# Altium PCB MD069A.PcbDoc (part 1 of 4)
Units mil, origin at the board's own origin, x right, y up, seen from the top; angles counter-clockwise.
Board outline 4569 x 3239 mil, 4 copper layers (Top Layer, Signal Layer 1, Signal Layer 2, Bottom Layer), stack 61.2 mil thick; 187 components, 103 nets, 560 pads, 220 vias.
Unrouted connection lines stored in the file: 7.
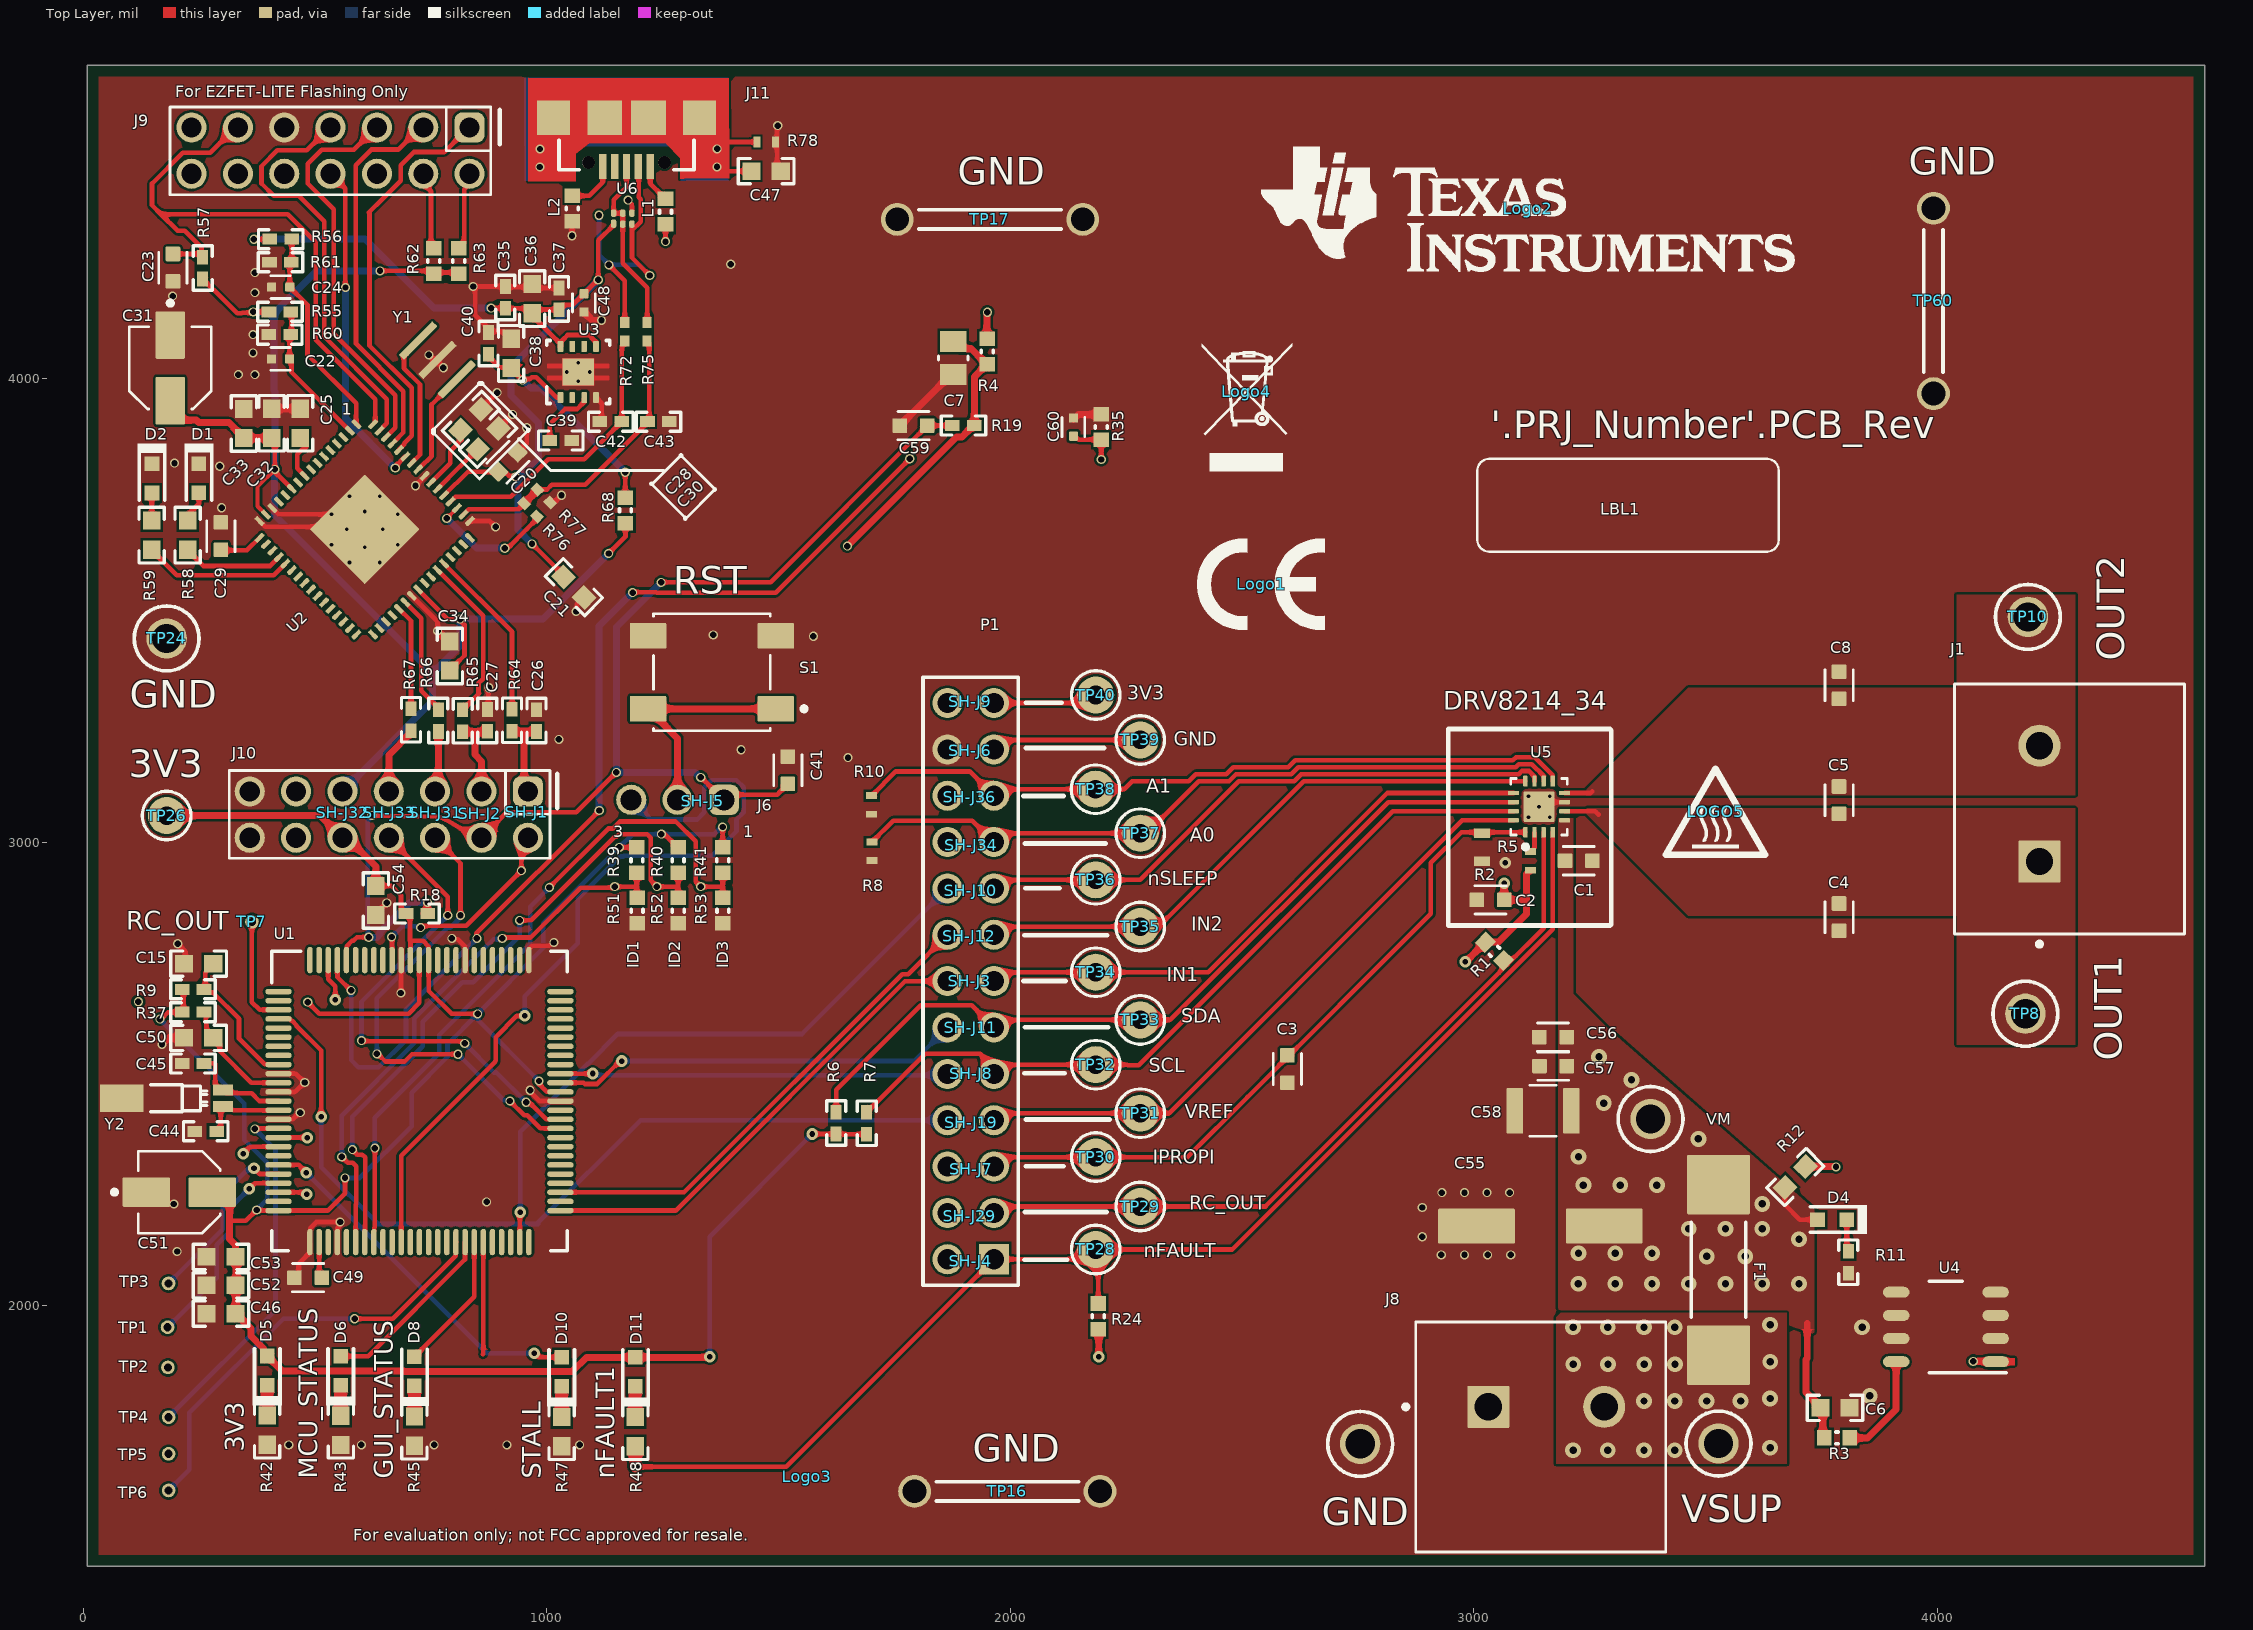
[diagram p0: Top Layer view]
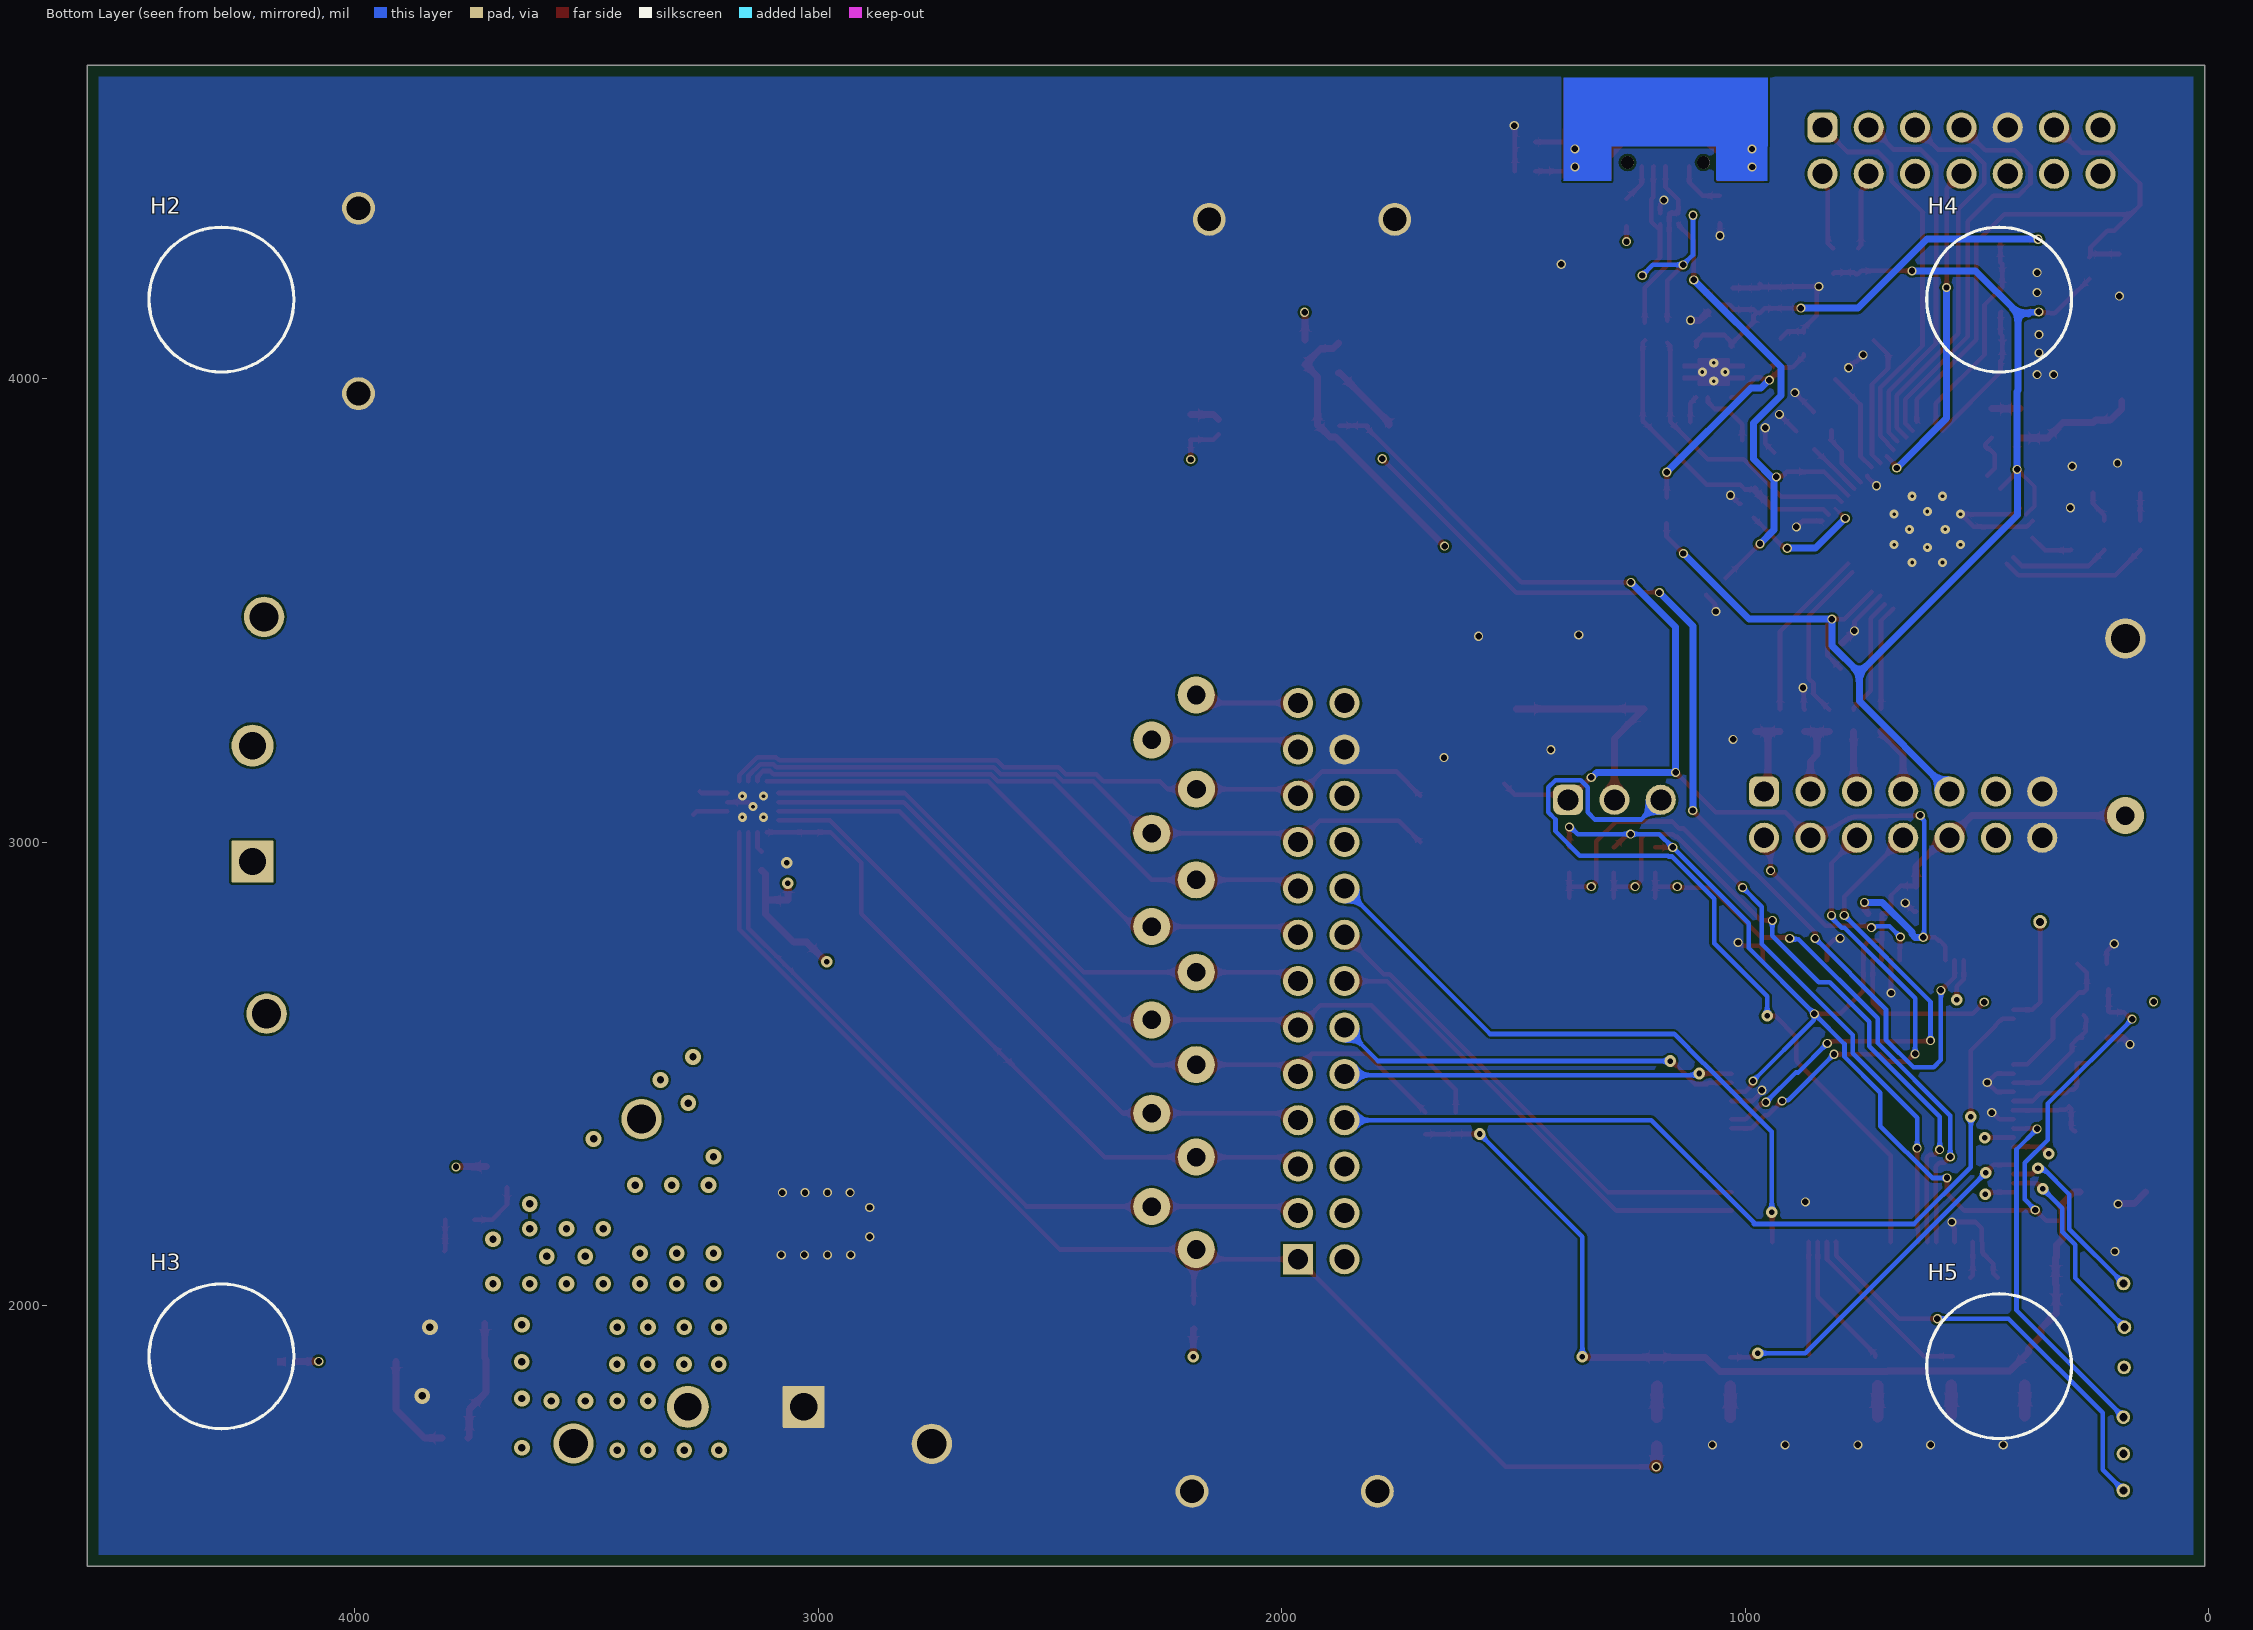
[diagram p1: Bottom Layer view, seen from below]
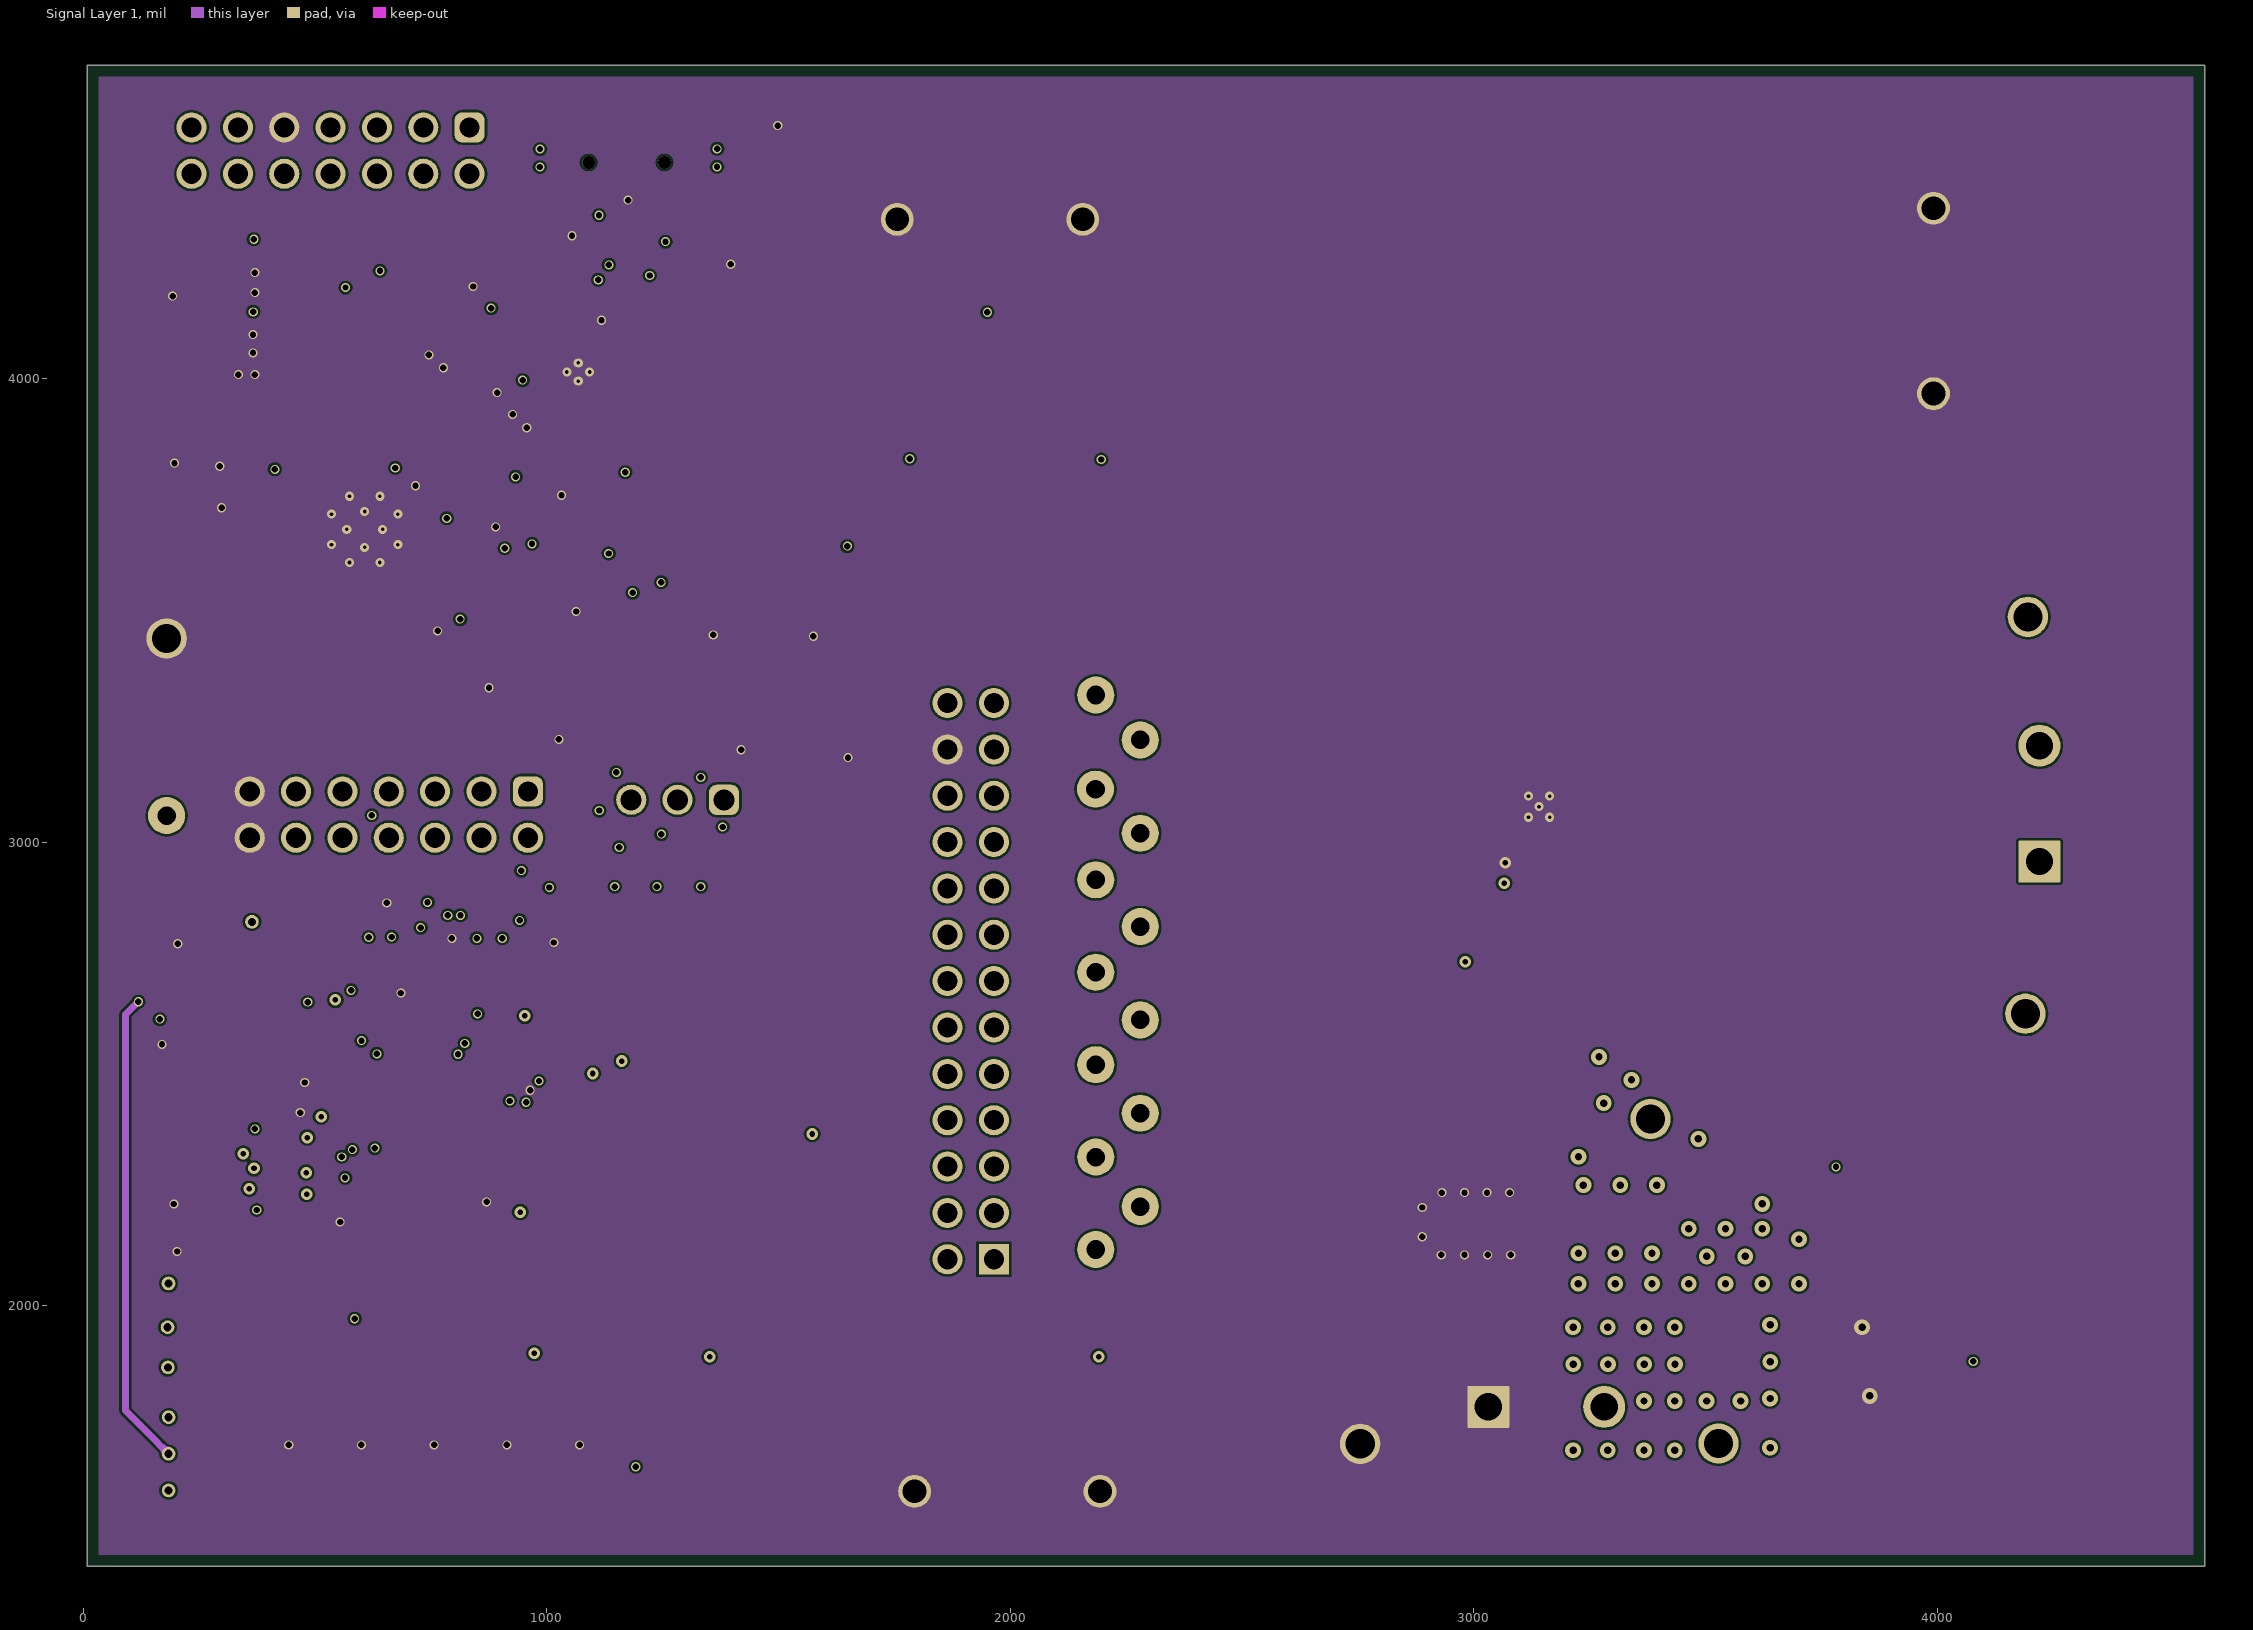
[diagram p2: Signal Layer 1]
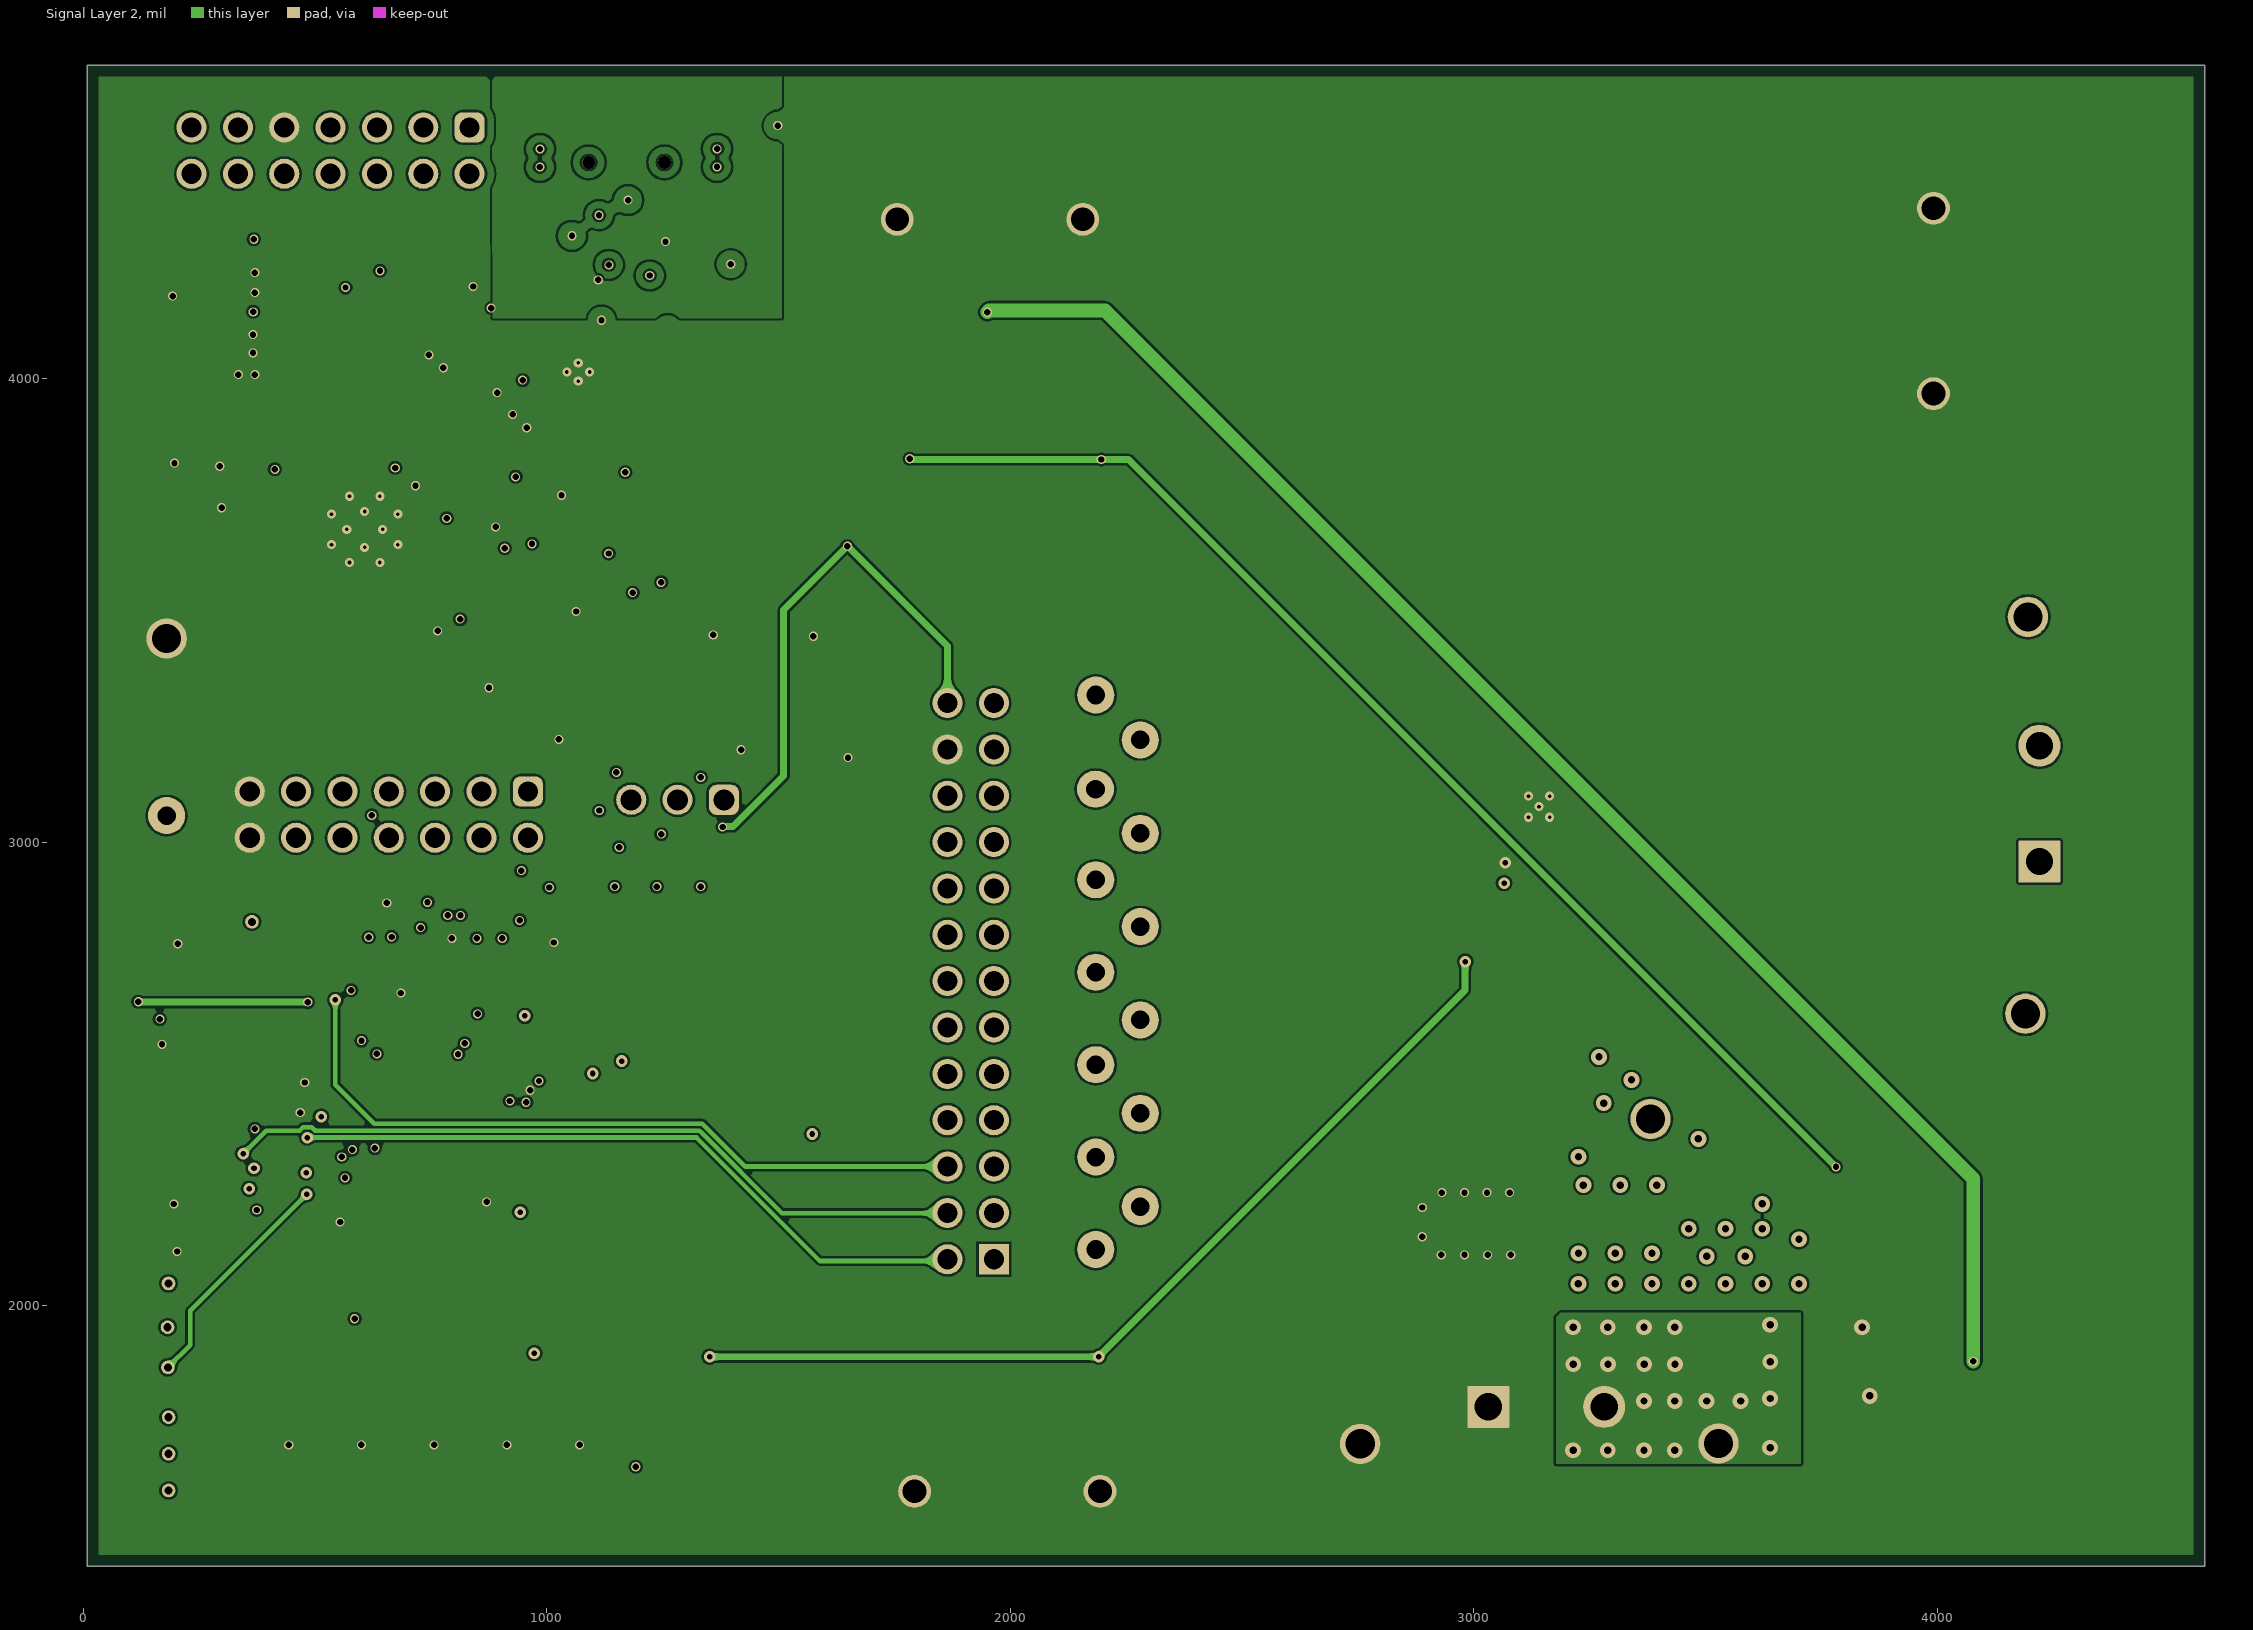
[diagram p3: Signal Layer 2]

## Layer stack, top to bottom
Top Solder: solder mask 0.4, Solder Resist, Dk 3.5
Top Layer: signal copper 2.8
Dielectric 1: prepreg 11.4, FR4 370, Dk 4.2
Signal Layer 1: signal copper 1.4
Dielectric 2: core 30, FR4 370, Dk 4.2
Signal Layer 2: signal copper 1.4
Dielectric 3: prepreg 11.4, FR4 370, Dk 4.2
Bottom Layer: signal copper 2.8
Bottom Solder: solder mask 0.4, Solder Resist, Dk 3.5

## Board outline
8,4677 8,1438 4577,1438 4577,4677

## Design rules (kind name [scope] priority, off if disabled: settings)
AcuteAngle [All] p1: minimum=4.50000000000000E+0001 checktracksonly=FALSE
AssemblyTestPointUsage [All] p1: valid=2
BoardOutlineClearance BoardOutlineClearance_MountingHoles [OnCopper and InComponentClass('Mounting Holes')] p1: gap=39.37 ignorepadtopadclearanceinfootprint=FALSE
BoardOutlineClearance BoardOutlineClearance_Poly [OnCopper and IsPoly] p2: gap=25 ignorepadtopadclearanceinfootprint=FALSE
BoardOutlineClearance [OnCopper and Not InComponentClass('Logo') and not InComponentClass('FiducialMark') and not InRegion(1000,500,4000,800) and not InPoly] p3: gap=75 ignorepadtopadclearanceinfootprint=FALSE
Clearance Clearance_92 [InNamedPolygon('TOP_LAYER_VM_P125')] p1: gap=8 ignorepadtopadclearanceinfootprint=TRUE
Clearance Clearance_93 [All] p2: gap=5 ignorepadtopadclearanceinfootprint=TRUE
Clearance Clearance_91 [InNamedPolygon('BOTTOM_LAYER_VM_P080')] p3: gap=10 ignorepadtopadclearanceinfootprint=TRUE except(0: Arc-Hole Track-Hole SMDPad-Hole THPad-Hole Via-Hole Fill-Hole Poly-Hole Region-Hole Text-Hole)
Clearance Clearance_90 [InNamedPolygon('BOTTOM_LAYER_OUT2_P211')] p4: gap=10 ignorepadtopadclearanceinfootprint=TRUE except(0: Arc-Hole Track-Hole SMDPad-Hole THPad-Hole Via-Hole Fill-Hole Poly-Hole Region-Hole Text-Hole)
Clearance Clearance_89 [InNamedPolygon('BOTTOM_LAYER_OUT1_P205')] p5: gap=10 ignorepadtopadclearanceinfootprint=TRUE except(0: Arc-Hole Track-Hole SMDPad-Hole THPad-Hole Via-Hole Fill-Hole Poly-Hole Region-Hole Text-Hole)
Clearance Clearance_88 [InNamedPolygon('BOTTOM_LAYER_OUT1_P205')] p6: gap=10 ignorepadtopadclearanceinfootprint=TRUE except(0: Arc-Hole Track-Hole SMDPad-Hole THPad-Hole Via-Hole Fill-Hole Poly-Hole Region-Hole Text-Hole)
Clearance Clearance_87 [InNamedPolygon('BOTTOM_LAYER_GND_P204')] p7: gap=10 ignorepadtopadclearanceinfootprint=TRUE except(0: Arc-Hole Track-Hole SMDPad-Hole THPad-Hole Via-Hole Fill-Hole Poly-Hole Region-Hole Text-Hole)
Clearance Clearance_86 [InNamedPolygon('TOP_LAYER_NONET_P237')] p8: gap=10 ignorepadtopadclearanceinfootprint=TRUE except(0: Arc-Hole Track-Hole SMDPad-Hole THPad-Hole Via-Hole Fill-Hole Poly-Hole Region-Hole Text-Hole)
Clearance Clearance_85 [InNamedPolygon('TOP_LAYER_VM_P229')] p9: gap=10 ignorepadtopadclearanceinfootprint=TRUE except(0: Arc-Hole Track-Hole SMDPad-Hole THPad-Hole Via-Hole Fill-Hole Poly-Hole Region-Hole Text-Hole)
Clearance Clearance_84 [InNamedPolygon('TOP_LAYER_GND_P086')] p10: gap=10 ignorepadtopadclearanceinfootprint=TRUE except(0: Arc-Hole Track-Hole SMDPad-Hole THPad-Hole Via-Hole Fill-Hole Poly-Hole Region-Hole Text-Hole)
Clearance Clearance_83 [InNamedPolygon('TOP_LAYER_OUT1_P221')] p11: gap=3.94 ignorepadtopadclearanceinfootprint=TRUE except(0: Arc-Hole Track-Hole SMDPad-Hole THPad-Hole Via-Hole Fill-Hole Poly-Hole Region-Hole Text-Hole)
Clearance Clearance_82 [InNamedPolygon('TOP_LAYER_OUT2_P173')] p12: gap=10 ignorepadtopadclearanceinfootprint=TRUE except(0: Arc-Hole Track-Hole SMDPad-Hole THPad-Hole Via-Hole Fill-Hole Poly-Hole Region-Hole Text-Hole)
Clearance Clearance_81 [InNamedPolygon('TOP_LAYER_OUT2_P173')] p13: gap=10 ignorepadtopadclearanceinfootprint=TRUE except(0: Arc-Hole Track-Hole SMDPad-Hole THPad-Hole Via-Hole Fill-Hole Poly-Hole Region-Hole Text-Hole)
Clearance Clearance_80 [InNamedPolygon('TOP_LAYER_OUT2_P173')] p14: gap=10 ignorepadtopadclearanceinfootprint=TRUE except(0: Arc-Hole Track-Hole SMDPad-Hole THPad-Hole Via-Hole Fill-Hole Poly-Hole Region-Hole Text-Hole)
Clearance Clearance_79 [InNamedPolygon('TOP_LAYER_OUT1_P221')] p15: gap=10 ignorepadtopadclearanceinfootprint=TRUE except(0: Arc-Hole Track-Hole SMDPad-Hole THPad-Hole Via-Hole Fill-Hole Poly-Hole Region-Hole Text-Hole)
Clearance Clearance_78 [InNamedPolygon('TOP_LAYER_GND_P086')] p16: gap=10 ignorepadtopadclearanceinfootprint=TRUE except(0: Arc-Hole Track-Hole SMDPad-Hole THPad-Hole Via-Hole Fill-Hole Poly-Hole Region-Hole Text-Hole)
Clearance Clearance_77 [InNamedPolygon('TOP_LAYER_OUT1_P129')] p17: gap=10 ignorepadtopadclearanceinfootprint=TRUE except(0: Arc-Hole Track-Hole SMDPad-Hole THPad-Hole Via-Hole Fill-Hole Poly-Hole Region-Hole Text-Hole)
Clearance Clearance_76 [InNamedPolygon('TOP_LAYER_OUT2_P173')] p18: gap=10 ignorepadtopadclearanceinfootprint=TRUE except(0: Arc-Hole Track-Hole SMDPad-Hole THPad-Hole Via-Hole Fill-Hole Poly-Hole Region-Hole Text-Hole)
Clearance Clearance_75 [InNamedPolygon('TOP_LAYER_VM_P085')] p19: gap=10 ignorepadtopadclearanceinfootprint=TRUE except(0: Arc-Hole Track-Hole SMDPad-Hole THPad-Hole Via-Hole Fill-Hole Poly-Hole Region-Hole Text-Hole)
Clearance Clearance_74 [InNamedPolygon('TOP_LAYER_GND_P121')] p20: gap=10 ignorepadtopadclearanceinfootprint=TRUE except(0: Arc-Hole Track-Hole SMDPad-Hole THPad-Hole Via-Hole Fill-Hole Poly-Hole Region-Hole Text-Hole)
Clearance Clearance_73 [InNamedPolygon('TOP_LAYER_OUT1_P129') Or  InNamedPolygon('TOP_LAYER_OUT2_P173')] p21: gap=1.97 ignorepadtopadclearanceinfootprint=TRUE except(0: Arc-Hole Track-Hole SMDPad-Hole THPad-Hole Via-Hole Fill-Hole Poly-Hole Region-Hole Text-Hole)
Clearance Clearance_72 [InNamedPolygon('TOP_LAYER_OUT2_P173') Or  InNamedPolygon('TOP_LAYER_OUT1_P129')] p22: gap=3.94 ignorepadtopadclearanceinfootprint=TRUE except(0: Arc-Hole Track-Hole SMDPad-Hole THPad-Hole Via-Hole Fill-Hole Poly-Hole Region-Hole Text-Hole)
Clearance Clearance_71 [InNamedPolygon('TOP_LAYER_OUT2_P173')] p23: gap=10 ignorepadtopadclearanceinfootprint=TRUE except(0: Arc-Hole Track-Hole SMDPad-Hole THPad-Hole Via-Hole Fill-Hole Poly-Hole Region-Hole Text-Hole)
Clearance Clearance_70 [InNamedPolygon('TOP_LAYER_OUT1_P129')] p24: gap=10 ignorepadtopadclearanceinfootprint=TRUE except(0: Arc-Hole Track-Hole SMDPad-Hole THPad-Hole Via-Hole Fill-Hole Poly-Hole Region-Hole Text-Hole)
Clearance Clearance_69 [InNamedPolygon('TOP_LAYER_OUT2_P173')] p25: gap=3.94 ignorepadtopadclearanceinfootprint=TRUE except(0: Arc-Hole Track-Hole SMDPad-Hole THPad-Hole Via-Hole Fill-Hole Poly-Hole Region-Hole Text-Hole)
Clearance Clearance_68 [InNamedPolygon('TOP_LAYER_OUT1_P129')] p26: gap=3.94 ignorepadtopadclearanceinfootprint=TRUE except(0: Arc-Hole Track-Hole SMDPad-Hole THPad-Hole Via-Hole Fill-Hole Poly-Hole Region-Hole Text-Hole)
Clearance Clearance_67 [InNamedPolygon('TOP_LAYER_VM_P085')] p27: gap=3.94 ignorepadtopadclearanceinfootprint=TRUE except(0: Arc-Hole Track-Hole SMDPad-Hole THPad-Hole Via-Hole Fill-Hole Poly-Hole Region-Hole Text-Hole)
Clearance Clearance_66 [InNamedPolygon('BOTTOM_LAYER_P_IN_P174')] p28: gap=10 ignorepadtopadclearanceinfootprint=TRUE except(0: Arc-Hole Track-Hole SMDPad-Hole THPad-Hole Via-Hole Fill-Hole Poly-Hole Region-Hole Text-Hole)
Clearance Clearance_65 [InNamedPolygon('BOTTOM_LAYER_NETF1_2_P203')] p29: gap=10 ignorepadtopadclearanceinfootprint=TRUE except(0: Arc-Hole Track-Hole SMDPad-Hole THPad-Hole Via-Hole Fill-Hole Poly-Hole Region-Hole Text-Hole)
Clearance Clearance_64 [InNamedPolygon('BOTTOM_LAYER_VBAT_P165')] p30: gap=10 ignorepadtopadclearanceinfootprint=TRUE except(0: Arc-Hole Track-Hole SMDPad-Hole THPad-Hole Via-Hole Fill-Hole Poly-Hole Region-Hole Text-Hole)
Clearance Clearance_63 [InNamedPolygon('TOP_LAYER_VM_P167')] p31: gap=10 ignorepadtopadclearanceinfootprint=TRUE except(0: Arc-Hole Track-Hole SMDPad-Hole THPad-Hole Via-Hole Fill-Hole Poly-Hole Region-Hole Text-Hole)
Clearance Clearance_62 [InNamedPolygon('TOP_LAYER_VM_P167')] p32: gap=10 ignorepadtopadclearanceinfootprint=TRUE except(0: Arc-Hole Track-Hole SMDPad-Hole THPad-Hole Via-Hole Fill-Hole Poly-Hole Region-Hole Text-Hole)
Clearance Clearance_61 [InNamedPolygon('TOP_LAYER_VM_P171')] p33: gap=10 ignorepadtopadclearanceinfootprint=TRUE except(0: Arc-Hole Track-Hole SMDPad-Hole THPad-Hole Via-Hole Fill-Hole Poly-Hole Region-Hole Text-Hole)
Clearance Clearance_60 [InNamedPolygon('SIGNAL_LAYER_2_NETF1_2_P196')] p34: gap=10 ignorepadtopadclearanceinfootprint=TRUE except(0: Arc-Hole Track-Hole SMDPad-Hole THPad-Hole Via-Hole Fill-Hole Poly-Hole Region-Hole Text-Hole)
Clearance Clearance_59 [InNamedPolygon('SIGNAL_LAYER_2_VBAT_P197')] p35: gap=10 ignorepadtopadclearanceinfootprint=TRUE except(0: Arc-Hole Track-Hole SMDPad-Hole THPad-Hole Via-Hole Fill-Hole Poly-Hole Region-Hole Text-Hole)
Clearance Clearance_58 [InNamedPolygon('SIGNAL_LAYER_2_P_IN_P198')] p36: gap=10 ignorepadtopadclearanceinfootprint=TRUE except(0: Arc-Hole Track-Hole SMDPad-Hole THPad-Hole Via-Hole Fill-Hole Poly-Hole Region-Hole Text-Hole)
Clearance Clearance_57 [InNamedPolygon('SIGNAL_LAYER_2_3V3_P194')] p37: gap=10 ignorepadtopadclearanceinfootprint=TRUE except(0: Arc-Hole Track-Hole SMDPad-Hole THPad-Hole Via-Hole Fill-Hole Poly-Hole Region-Hole Text-Hole)
Clearance Clearance_56 [InNamedPolygon('TOP_LAYER_NETF1_2_P207')] p38: gap=10 ignorepadtopadclearanceinfootprint=TRUE except(0: Arc-Hole Track-Hole SMDPad-Hole THPad-Hole Via-Hole Fill-Hole Poly-Hole Region-Hole Text-Hole)
Clearance Clearance_55 [InNamedPolygon('TOP_LAYER_VBAT_P223')] p39: gap=10 ignorepadtopadclearanceinfootprint=TRUE except(0: Arc-Hole Track-Hole SMDPad-Hole THPad-Hole Via-Hole Fill-Hole Poly-Hole Region-Hole Text-Hole)
Clearance Clearance_54 [InNamedPolygon('TOP_LAYER_P_IN_P227')] p40: gap=10 ignorepadtopadclearanceinfootprint=TRUE except(0: Arc-Hole Track-Hole SMDPad-Hole THPad-Hole Via-Hole Fill-Hole Poly-Hole Region-Hole Text-Hole)
Clearance Clearance_53 [InNamedPolygon('TOP_LAYER_GND_P086')] p41: gap=10 ignorepadtopadclearanceinfootprint=TRUE except(0: Arc-Hole Track-Hole SMDPad-Hole THPad-Hole Via-Hole Fill-Hole Poly-Hole Region-Hole Text-Hole)
Clearance Clearance_52 [InNamedPolygon('SIGNAL_LAYER_2_VM_P177') Or  InNamedPolygon('SIGNAL_LAYER_2_VM_P179') Or  InNamedPolygon('SIGNAL_LAYER_2_VM_P160') Or  InNamedPolygon('SIGNAL_LAYER_2_VM_P175') Or  InNamedPolygon('SIGNAL_LAYER_2_VM_P181')] p42: gap=10 ignorepadtopadclearanceinfootprint=TRUE except(0: Arc-Hole Track-Hole SMDPad-Hole THPad-Hole Via-Hole Fill-Hole Poly-Hole Region-Hole Text-Hole)
Clearance Clearance_51 [InNamedPolygon('SIGNAL_LAYER_2_EZFET_VBUS_P136')] p43: gap=10 ignorepadtopadclearanceinfootprint=TRUE except(0: Arc-Hole Track-Hole SMDPad-Hole THPad-Hole Via-Hole Fill-Hole Poly-Hole Region-Hole Text-Hole)
Clearance Clearance_50 [InNamedPolygon('SIGNAL_LAYER_2_EZFET_VCC_P132')] p44: gap=10 ignorepadtopadclearanceinfootprint=TRUE except(0: Arc-Hole Track-Hole SMDPad-Hole THPad-Hole Via-Hole Fill-Hole Poly-Hole Region-Hole Text-Hole)
Clearance Clearance_49 [InNamedPolygon('SIGNAL_LAYER_2_MCU_3V3_P192')] p45: gap=10 ignorepadtopadclearanceinfootprint=TRUE except(0: Arc-Hole Track-Hole SMDPad-Hole THPad-Hole Via-Hole Fill-Hole Poly-Hole Region-Hole Text-Hole)
Clearance Clearance_48 [InNamedPolygon('SIGNAL_LAYER_1_GND_P190')] p46: gap=10 ignorepadtopadclearanceinfootprint=TRUE except(0: Arc-Hole Track-Hole SMDPad-Hole THPad-Hole Via-Hole Fill-Hole Poly-Hole Region-Hole Text-Hole)
Clearance Clearance_47 [InNamedPolygon('SIGNAL_LAYER_1_GND_P184')] p47: gap=10 ignorepadtopadclearanceinfootprint=TRUE except(0: Arc-Hole Track-Hole SMDPad-Hole THPad-Hole Via-Hole Fill-Hole Poly-Hole Region-Hole Text-Hole)
Clearance Clearance_46 [InNamedPolygon('BOTTOM_LAYER_GND_P241')] p48: gap=10 ignorepadtopadclearanceinfootprint=TRUE except(0: Arc-Hole Track-Hole SMDPad-Hole THPad-Hole Via-Hole Fill-Hole Poly-Hole Region-Hole Text-Hole)
Clearance Clearance_45 [InNamedPolygon('BOTTOM_LAYER_GND_P241')] p49: gap=10 ignorepadtopadclearanceinfootprint=TRUE except(0: Arc-Hole Track-Hole SMDPad-Hole THPad-Hole Via-Hole Fill-Hole Poly-Hole Region-Hole Text-Hole)
Clearance Clearance_44 [InNamedPolygon('BOTTOM_LAYER_OUT2_P163')] p50: gap=10 ignorepadtopadclearanceinfootprint=TRUE except(0: Arc-Hole Track-Hole SMDPad-Hole THPad-Hole Via-Hole Fill-Hole Poly-Hole Region-Hole Text-Hole)
Clearance Clearance_43 [InNamedPolygon('BOTTOM_LAYER_VM_P166')] p51: gap=10 ignorepadtopadclearanceinfootprint=TRUE except(0: Arc-Hole Track-Hole SMDPad-Hole THPad-Hole Via-Hole Fill-Hole Poly-Hole Region-Hole Text-Hole)
Clearance Clearance_42 [InNamedPolygon('BOTTOM_LAYER_VM_P235')] p52: gap=10 ignorepadtopadclearanceinfootprint=TRUE except(0: Arc-Hole Track-Hole SMDPad-Hole THPad-Hole Via-Hole Fill-Hole Poly-Hole Region-Hole Text-Hole)
Clearance Clearance_41 [InNamedPolygon('BOTTOM_LAYER_OUT1_P164')] p53: gap=10 ignorepadtopadclearanceinfootprint=TRUE except(0: Arc-Hole Track-Hole SMDPad-Hole THPad-Hole Via-Hole Fill-Hole Poly-Hole Region-Hole Text-Hole)
Clearance Clearance_40 [InNamedPolygon('BOTTOM_LAYER_GND_P162')] p54: gap=10 ignorepadtopadclearanceinfootprint=TRUE except(0: Arc-Hole Track-Hole SMDPad-Hole THPad-Hole Via-Hole Fill-Hole Poly-Hole Region-Hole Text-Hole)
Clearance Clearance_39 [InNamedPolygon('SIGNAL_LAYER_2_VM_P160')] p55: gap=10 ignorepadtopadclearanceinfootprint=TRUE except(0: Arc-Hole Track-Hole SMDPad-Hole THPad-Hole Via-Hole Fill-Hole Poly-Hole Region-Hole Text-Hole)
Clearance Clearance_38 [InNamedPolygon('SIGNAL_LAYER_2_NONET_P138')] p56: gap=10 ignorepadtopadclearanceinfootprint=TRUE except(0: Arc-Hole Track-Hole SMDPad-Hole THPad-Hole Via-Hole Fill-Hole Poly-Hole Region-Hole Text-Hole)
Clearance Clearance_37 [InNamedPolygon('SIGNAL_LAYER_1_VM_P146')] p57: gap=10 ignorepadtopadclearanceinfootprint=TRUE except(0: Arc-Hole Track-Hole SMDPad-Hole THPad-Hole Via-Hole Fill-Hole Poly-Hole Region-Hole Text-Hole)
Clearance Clearance_36 [InNamedPolygon('SIGNAL_LAYER_2_GND_P156')] p58: gap=10 ignorepadtopadclearanceinfootprint=TRUE except(0: Arc-Hole Track-Hole SMDPad-Hole THPad-Hole Via-Hole Fill-Hole Poly-Hole Region-Hole Text-Hole)
Clearance Clearance_35 [InNamedPolygon('SIGNAL_LAYER_1_VM_P148') Or  InNamedPolygon('SIGNAL_LAYER_1_VM_P148')] p59: gap=10 ignorepadtopadclearanceinfootprint=TRUE except(0: Arc-Hole Track-Hole SMDPad-Hole THPad-Hole Via-Hole Fill-Hole Poly-Hole Region-Hole Text-Hole)
Clearance Clearance_34 [InNamedPolygon('SIGNAL_LAYER_1_GND_P154')] p60: gap=10 ignorepadtopadclearanceinfootprint=TRUE except(0: Arc-Hole Track-Hole SMDPad-Hole THPad-Hole Via-Hole Fill-Hole Poly-Hole Region-Hole Text-Hole)
Clearance Clearance_33 [InNamedPolygon('SIGNAL_LAYER_2_NONET_P138')] p61: gap=10 ignorepadtopadclearanceinfootprint=TRUE except(0: Arc-Hole Track-Hole SMDPad-Hole THPad-Hole Via-Hole Fill-Hole Poly-Hole Region-Hole Text-Hole)
Clearance Clearance_32 [InNamedPolygon('SIGNAL_LAYER_2_GND_P082')] p62: gap=10 ignorepadtopadclearanceinfootprint=TRUE except(0: Arc-Hole Track-Hole SMDPad-Hole THPad-Hole Via-Hole Fill-Hole Poly-Hole Region-Hole Text-Hole)
Clearance Clearance_31 [InNamedPolygon('TOP_LAYER_GND_P076')] p63: gap=10 ignorepadtopadclearanceinfootprint=TRUE except(0: Arc-Hole Track-Hole SMDPad-Hole THPad-Hole Via-Hole Fill-Hole Poly-Hole Region-Hole Text-Hole)
Clearance Clearance_30 [InNamedPolygon('TOP_LAYER_GND_P087')] p64: gap=10 ignorepadtopadclearanceinfootprint=TRUE except(0: Arc-Hole Track-Hole SMDPad-Hole THPad-Hole Via-Hole Fill-Hole Poly-Hole Region-Hole Text-Hole)
Clearance Clearance_29 [InNamedPolygon('TOP_LAYER_VM_P127') Or  InNamedPolygon('TOP_LAYER_VM_P085')] p65: gap=10 ignorepadtopadclearanceinfootprint=TRUE except(0: Arc-Hole Track-Hole SMDPad-Hole THPad-Hole Via-Hole Fill-Hole Poly-Hole Region-Hole Text-Hole)
Clearance Clearance_28 [InNamedPolygon('TOP_LAYER_GND_P117')] p66: gap=10 ignorepadtopadclearanceinfootprint=TRUE except(0: Arc-Hole Track-Hole SMDPad-Hole THPad-Hole Via-Hole Fill-Hole Poly-Hole Region-Hole Text-Hole)
Clearance Clearance_27 [InNamedPolygon('TOP_LAYER_OUT1_P129') Or  InNamedPolygon('TOP_LAYER_OUT2_P173')] p67: gap=10 ignorepadtopadclearanceinfootprint=TRUE except(0: Arc-Hole Track-Hole SMDPad-Hole THPad-Hole Via-Hole Fill-Hole Poly-Hole Region-Hole Text-Hole)
Clearance Clearance_26 [InNamedPolygon('SIGNAL_LAYER_2_NONET_P113')] p68: gap=10 ignorepadtopadclearanceinfootprint=TRUE except(0: Arc-Hole Track-Hole SMDPad-Hole THPad-Hole Via-Hole Fill-Hole Poly-Hole Region-Hole Text-Hole)
Clearance Clearance_25 [InNamedPolygon('BOTTOM_LAYER_NONET_P115')] p69: gap=10 ignorepadtopadclearanceinfootprint=TRUE except(0: Arc-Hole Track-Hole SMDPad-Hole THPad-Hole Via-Hole Fill-Hole Poly-Hole Region-Hole Text-Hole)
Clearance Clearance_24 [InNamedPolygon('SIGNAL_LAYER_1_NONET_P111')] p70: gap=10 ignorepadtopadclearanceinfootprint=TRUE except(0: Arc-Hole Track-Hole SMDPad-Hole THPad-Hole Via-Hole Fill-Hole Poly-Hole Region-Hole Text-Hole)
Clearance Clearance_23 [InNamedPolygon('TOP_LAYER_NONET_P083')] p71: gap=10 ignorepadtopadclearanceinfootprint=TRUE except(0: Arc-Hole Track-Hole SMDPad-Hole THPad-Hole Via-Hole Fill-Hole Poly-Hole Region-Hole Text-Hole)
Clearance Clearance_22 [InNamedPolygon('TOP_LAYER_NONET_P105')] p72: gap=10 ignorepadtopadclearanceinfootprint=TRUE except(0: Arc-Hole Track-Hole SMDPad-Hole THPad-Hole Via-Hole Fill-Hole Poly-Hole Region-Hole Text-Hole)
Clearance Clearance_21 [InNamedPolygon('TOP_LAYER_OUT2_P107')] p73: gap=10 ignorepadtopadclearanceinfootprint=TRUE except(0: Arc-Hole Track-Hole SMDPad-Hole THPad-Hole Via-Hole Fill-Hole Poly-Hole Region-Hole Text-Hole)
Clearance Clearance_20 [InNamedPolygon('TOP_LAYER_NONET_P101')] p74: gap=10 ignorepadtopadclearanceinfootprint=TRUE except(0: Arc-Hole Track-Hole SMDPad-Hole THPad-Hole Via-Hole Fill-Hole Poly-Hole Region-Hole Text-Hole)
Clearance Clearance_19 [InNamedPolygon('TOP_LAYER_OUT1_P103')] p75: gap=10 ignorepadtopadclearanceinfootprint=TRUE except(0: Arc-Hole Track-Hole SMDPad-Hole THPad-Hole Via-Hole Fill-Hole Poly-Hole Region-Hole Text-Hole)
Clearance Clearance_18 [InNet('OUT1')] p76: gap=10 ignorepadtopadclearanceinfootprint=TRUE except(0: Arc-Hole Track-Hole SMDPad-Hole THPad-Hole Via-Hole Fill-Hole Poly-Hole Region-Hole Text-Hole)
Clearance Clearance_17 [InNamedPolygon('TOP_LAYER_OUT1_P000')] p77: gap=10 ignorepadtopadclearanceinfootprint=TRUE except(0: Arc-Hole Track-Hole SMDPad-Hole THPad-Hole Via-Hole Fill-Hole Poly-Hole Region-Hole Text-Hole)
Clearance Clearance_16 [InNamedPolygon('TOP_LAYER_OUT1_P000') vs InNet('OUT1')] p78: gap=3.94 ignorepadtopadclearanceinfootprint=TRUE except(0: Arc-Hole Track-Hole SMDPad-Hole THPad-Hole Via-Hole Fill-Hole Poly-Hole Region-Hole Text-Hole)
Clearance Clearance_15 [InNamedPolygon('TOP_LAYER_OUT1_P000')] p79: gap=3.94 ignorepadtopadclearanceinfootprint=TRUE except(0: Arc-Hole Track-Hole SMDPad-Hole THPad-Hole Via-Hole Fill-Hole Poly-Hole Region-Hole Text-Hole)
Clearance Clearance_14 [InNamedPolygon('TOP_LAYER_NONET_P093')] p80: gap=3.94 ignorepadtopadclearanceinfootprint=TRUE except(0: Arc-Hole Track-Hole SMDPad-Hole THPad-Hole Via-Hole Fill-Hole Poly-Hole Region-Hole Text-Hole)
Clearance Clearance_13 [InNamedPolygon('TOP_LAYER_NONET_P093')] p81: gap=10 ignorepadtopadclearanceinfootprint=TRUE except(0: Arc-Hole Track-Hole SMDPad-Hole THPad-Hole Via-Hole Fill-Hole Poly-Hole Region-Hole Text-Hole)
Clearance Clearance_12 [InNamedPolygon('TOP_LAYER_OUT2_P099')] p82: gap=10 ignorepadtopadclearanceinfootprint=TRUE except(0: Arc-Hole Track-Hole SMDPad-Hole THPad-Hole Via-Hole Fill-Hole Poly-Hole Region-Hole Text-Hole)
Clearance Clearance_11 [InNamedPolygon('TOP_LAYER_OUT2_P099')] p83: gap=10 ignorepadtopadclearanceinfootprint=TRUE except(0: Arc-Hole Track-Hole SMDPad-Hole THPad-Hole Via-Hole Fill-Hole Poly-Hole Region-Hole Text-Hole)
Clearance Clearance_10 [InNamedPolygon('TOP_LAYER_OUT1_P000')] p84: gap=10 ignorepadtopadclearanceinfootprint=TRUE except(0: Arc-Hole Track-Hole SMDPad-Hole THPad-Hole Via-Hole Fill-Hole Poly-Hole Region-Hole Text-Hole)
Clearance Clearance_9 [InNamedPolygon('TOP_LAYER_OUT1_P000')] p85: gap=10 ignorepadtopadclearanceinfootprint=TRUE except(0: Arc-Hole Track-Hole SMDPad-Hole THPad-Hole Via-Hole Fill-Hole Poly-Hole Region-Hole Text-Hole)
Clearance Clearance_8 [InNamedPolygon('BOTTOM_LAYER_NONET_P079') Or  InNamedPolygon('SIGNAL_LAYER_2_NONET_P078') Or  InNamedPolygon('SIGNAL_LAYER_1_NONET_P077') Or  InNamedPolygon('TOP_LAYER_NONET_P083') Or  InNamedPolygon('BOTTOM_LAYER_NONET_P072') Or  InNamedPolygon('SIGNAL_LAYER_2_NONET_P070') Or  InNamedPolygon('SIGNAL_LAYER_1_NONET_P059') Or  InNamedPolygon('TOP_LAYER_OUT2_P058') Or  InNamedPolygon('BOTTOM_LAYER_NONET_P056') Or  InNamedPolygon('SIGNAL_LAYER_2_NONET_P054') Or  InNamedPolygon('SIGNAL_LAYER_1_NONET_P052') Or  InNamedPolygon('TOP_LAYER_OUT1_P050') Or  InNamedPolygon('BOTTOM_LAYER_VM_P044') Or  InNamedPolygon('SIGNAL_LAYER_2_VM_P042') Or  InNamedPolygon('SIGNAL_LAYER_1_VM_P040') Or  InNamedPolygon('TOP_LAYER_VM_P038') Or  InNamedPolygon('BOTTOM_LAYER_VM_P036') Or  InNamedPolygon('SIGNAL_LAYER_2_VM_P018') Or  InNamedPolygon('SIGNAL_LAYER_1_VM_P016') Or  InNamedPolygon('TOP_LAYER_VM_P002')] p86: gap=10 ignorepadtopadclearanceinfootprint=TRUE except(0: Arc-Hole Track-Hole SMDPad-Hole THPad-Hole Via-Hole Fill-Hole Poly-Hole Region-Hole Text-Hole)
Clearance Clearance_7 [InNamedPolygon('TOP_LAYER_NONET_P089') Or  InNamedPolygon('TOP_LAYER_NONET_P090')] p87: gap=10 ignorepadtopadclearanceinfootprint=TRUE except(0: Arc-Hole Track-Hole SMDPad-Hole THPad-Hole Via-Hole Fill-Hole Poly-Hole Region-Hole Text-Hole)
Clearance Clearance_6 [InNamedPolygon('BOTTOM_LAYER_EZFET_USB_SHIELD_P002') Or  InNamedPolygon('TOP_LAYER_EZFET_USB_SHIELD_P201') Or  InNamedPolygon('SIGNAL_LAYER_2_EZFET_VBUS_P018') Or  InNamedPolygon('SIGNAL_LAYER_2_EZFET_VCC_P016')] p88: gap=10 ignorepadtopadclearanceinfootprint=TRUE except(0: Arc-Hole Track-Hole SMDPad-Hole THPad-Hole Via-Hole Fill-Hole Poly-Hole Region-Hole Text-Hole)
Clearance Clearance_5 [InNamedPolygon('TOP_LAYER_NONET_P072')] p89: gap=10 ignorepadtopadclearanceinfootprint=TRUE except(0: Arc-Hole Track-Hole SMDPad-Hole THPad-Hole Via-Hole Fill-Hole Poly-Hole Region-Hole Text-Hole)
Clearance Clearance_4 [InNamedPolygon('TOP_LAYER_VM_P123') Or  InNamedPolygon('TOP_LAYER_VM_P123') Or  InNamedPolygon('TOP_LAYER_VM_P123')] p90: gap=10 ignorepadtopadclearanceinfootprint=TRUE except(0: Arc-Hole Track-Hole SMDPad-Hole THPad-Hole Via-Hole Fill-Hole Poly-Hole Region-Hole Text-Hole)
Clearance Clearance_3 [InNamedPolygon('TOP_LAYER_VM_P042') Or  InNamedPolygon('TOP_LAYER_VM_P044') Or  InNamedPolygon('TOP_LAYER_OUT2_P040') Or  InNamedPolygon('TOP_LAYER_OUT1_P038')] p91: gap=10 ignorepadtopadclearanceinfootprint=TRUE except(0: Arc-Hole Track-Hole SMDPad-Hole THPad-Hole Via-Hole Fill-Hole Poly-Hole Region-Hole Text-Hole)
Clearance Clearance_2 [InNamedPolygon('TOP_LAYER_OUT2_P040')] p92: gap=10 ignorepadtopadclearanceinfootprint=TRUE except(0: Arc-Hole Track-Hole SMDPad-Hole THPad-Hole Via-Hole Fill-Hole Poly-Hole Region-Hole Text-Hole)
Clearance Clearance_1 [InNamedPolygon('TOP_LAYER_VM_P046')] p93: gap=5.98 ignorepadtopadclearanceinfootprint=TRUE except(0: Arc-Hole Track-Hole SMDPad-Hole THPad-Hole Via-Hole Fill-Hole Poly-Hole Region-Hole Text-Hole)
Clearance Clearance_Keepouts [((IsTrack Or IsArc) And Not InPoly) And IsFree and IsKeepOut vs ((IsTrack Or IsArc) And Not InPoly) And IsFree and IsKeepOut] p94: gap=0 ignorepadtopadclearanceinfootprint=FALSE
Clearance Clearance_Poly [InPolygon] p95: gap=25 ignorepadtopadclearanceinfootprint=TRUE
Clearance Clearance_FiducialMark [IsKeepOut and InComponentClass('FiducialMark') vs IsPad and InComponentClass('FiducialMark')] p96: gap=0 ignorepadtopadclearanceinfootprint=FALSE
Clearance [All] p97: gap=7.87 ignorepadtopadclearanceinfootprint=TRUE
ComponentClearance ComponentClearance_MountingHoles_FiducialMarks [InComponentClass('Mounting Holes') vs InComponentClass('FiducialMark')] p1: gap=50 collisioncheckmode=3 verticalgap=10 showdistances=FALSE
ComponentClearance ComponentClearance_Shunt [InComponentClass('Header') vs InComponentClass('Shunt')] p2: gap=0 collisioncheckmode=3 verticalgap=0 showdistances=FALSE
ComponentClearance ComponentClearance_Logo [InComponentClass('Logo')] p3: gap=50 collisioncheckmode=3 verticalgap=10 showdistances=FALSE
ComponentClearance ComponentClearance_ScrewToNut [(HasFootprint('NY PMS 440 0025 PH')) vs (HasFootprint('Keystone_1902C'))] p4: gap=5 collisioncheckmode=3 verticalgap=10 showdistances=FALSE
ComponentClearance ComponentClearance_MountingHoles [InComponentClass('Mounting Holes')] p5: gap=250 collisioncheckmode=3 verticalgap=100000 showdistances=FALSE
ComponentClearance ComponentClearance_SmallPassives [HasFootprint('0201*') or HasFootprint('0402*') or HasFootprint('0508') or HasFootprint('0603*') or HasFootprint('0612') or HasFootprint('0805*') or HasFootprint('0815*') or HasFootprint('0830*') or HasFootprint('1206*') or HasFootprint('1210*') or HasFootprint('1808*') or HasFootprint('1812*') or HasFootprint('1825*') or HasFootprint('2010*') or HasFootprint('2220*') or HasFootprint('2225*') or HasFootprint('2512*') or HasFootprint('2728*') or HasFootprint('3518*') vs HasFootprint('0201*') or HasFootprint('0402*') or HasFootprint('0508') or HasFootprint('0603*') or HasFootprint('0612') or HasFootprint('0805*') or HasFootprint('0815*') or HasFootprint('0830*') or HasFootprint('1206*') or HasFootprint('1210*') or HasFootprint('1808*') or HasFootprint('1812*') or HasFootprint('1825*') or HasFootprint('2010*') or HasFootprint('2220*') or HasFootprint('2225*') or HasFootprint('2512*') or HasFootprint('2728*') or HasFootprint('3518*')] p6: gap=14.96 collisioncheckmode=3 verticalgap=10 showdistances=FALSE
ComponentClearance ComponentClearance_THtoSMT [IsThruComponent vs IsSMTComponent] p7: gap=40 collisioncheckmode=3 verticalgap=30 showdistances=FALSE
ComponentClearance ComponentClearance_THtoTH [IsThruComponent vs IsThruComponent] p8: gap=30 collisioncheckmode=3 verticalgap=30 showdistances=FALSE
ComponentClearance [All] p9: gap=30 collisioncheckmode=3 verticalgap=10 showdistances=FALSE
DiffPairsRouting [All] p1: maxlimit=100 minlimit=10 mostfreqgap=10 toplayer_minwidth=6.3 toplayer_maxwidth=15 toplayer_prefwidth=10 midlayer1_minwidth=15 midlayer1_maxwidth=15 midlayer1_prefwidth=15 midlayer2_minwidth=15 midlayer2_maxwidth=15 midlayer2_prefwidth=15 bottomlayer_minwidth=6.3 bottomlayer_maxwidth=15 bottomlayer_prefwidth=10 maxuncoupledlength=1000
FabricationTestPointUsage TestPointUsage [All] p1: valid=2 allowmultiple=FALSE
FabricationTestpoint Testpoint [All] p1: side=3 testpointundercomponent=TRUE minsize=40 maxsize=100 preferedsize=60 minholesize=0 maxholesize=40 preferedholesize=32 testpointgrid=1 allowsidetop=TRUE allowsidebottom=TRUE usegrid=TRUE gridtolerance=0.01
FanoutControl Fanout_LCC [IsLCC] p1: bgadir=Out bgaviamode=Centered fanoutstyle=Auto fanoutdirection=Alternating viagrid=1 // Fanout_LCC (Default Rule)
FanoutControl Fanout_BGA [IsBGA] p2: bgadir=Out bgaviamode=Centered fanoutstyle=Auto fanoutdirection=Alternating viagrid=1 // Fanout_BGA (Default Rule)
FanoutControl Fanout_Default [All] p4: bgadir=Out bgaviamode=Centered fanoutstyle=Auto fanoutdirection=Alternating viagrid=1 // Fanout_Default (Default Rule)
FanoutControl Fanout_Small [(CompPinCount < 5)] p5: bgadir=Out bgaviamode=Centered fanoutstyle=Auto fanoutdirection=OutThenIn viagrid=1 // Fanout_Small (Default Rule)
HoleSize [All] p1: absolutevalues=TRUE maxlimit=251 minlimit=7.87 maxpercent=80.000 minpercent=20.000
MinimumAnnularRing MinimumAnnularRing_ThermalPadVias [IsVia and InAnyComponent] p1: minimumring=5.91
MinimumAnnularRing [All] p2: minimumring=7.87
MinimumSolderMaskSliver MinimumSolderMaskSliver_Logo [InComponentClass('Logo') vs InComponentClass('Logo')] p1: minsoldermaskwidth=0.7
MinimumSolderMaskSliver [All] p2: minsoldermaskwidth=3.94
PlaneConnect [All] p1: planeconnectstyle=Direct reliefexpansion=10 reliefentries=4 reliefconductorwidth=10 reliefairgap=10
PolygonConnect PolygonConnect_94 [All vs IsNamedPolygon('BOTTOM_LAYER_GND_P203')] p1: thpad.connectstyle=Direct thpad.reliefconductorwidth=10 thpad.reliefentries=4 thpad.polygonreliefangle="90 Angle" thpad.airgapwidth=10 smdpad.connectstyle=Direct smdpad.reliefconductorwidth=10 smdpad.reliefentries=4 smdpad.polygonreliefangle="90 Angle" smdpad.airgapwidth=10 via.connectstyle=Relief via.reliefconductorwidth=10 via.reliefentries=4 via.polygonreliefangle="90 Angle" via.airgapwidth=10
PolygonConnect PolygonConnect_93 [All vs IsNamedPolygon('SIGNAL_LAYER_2_EZFET_VBUS_P136')] p2: thpad.connectstyle=Direct thpad.reliefconductorwidth=10 thpad.reliefentries=4 thpad.polygonreliefangle="90 Angle" thpad.airgapwidth=10 smdpad.connectstyle=Direct smdpad.reliefconductorwidth=10 smdpad.reliefentries=4 smdpad.polygonreliefangle="90 Angle" smdpad.airgapwidth=10 via.connectstyle=Relief via.reliefconductorwidth=10 via.reliefentries=4 via.polygonreliefangle="90 Angle" via.airgapwidth=10
PolygonConnect PolygonConnect_92 [All vs IsNamedPolygon('TOP_LAYER_VM_P244')] p3: thpad.connectstyle=Direct thpad.reliefconductorwidth=10 thpad.reliefentries=4 thpad.polygonreliefangle="90 Angle" thpad.airgapwidth=10 smdpad.connectstyle=Direct smdpad.reliefconductorwidth=10 smdpad.reliefentries=4 smdpad.polygonreliefangle="90 Angle" smdpad.airgapwidth=10 via.connectstyle=Relief via.reliefconductorwidth=10 via.reliefentries=4 via.polygonreliefangle="90 Angle" via.airgapwidth=10
PolygonConnect PolygonConnect_91 [All vs IsNamedPolygon('TOP_LAYER_BOUT2_P242')] p4: thpad.connectstyle=Direct thpad.reliefconductorwidth=10 thpad.reliefentries=4 thpad.polygonreliefangle="90 Angle" thpad.airgapwidth=10 smdpad.connectstyle=Direct smdpad.reliefconductorwidth=10 smdpad.reliefentries=4 smdpad.polygonreliefangle="90 Angle" smdpad.airgapwidth=10 via.connectstyle=Relief via.reliefconductorwidth=10 via.reliefentries=4 via.polygonreliefangle="90 Angle" via.airgapwidth=10
PolygonConnect PolygonConnect_90 [All vs IsNamedPolygon('TOP_LAYER_VM_P239')] p5: thpad.connectstyle=Direct thpad.reliefconductorwidth=10 thpad.reliefentries=4 thpad.polygonreliefangle="90 Angle" thpad.airgapwidth=10 smdpad.connectstyle=Direct smdpad.reliefconductorwidth=10 smdpad.reliefentries=4 smdpad.polygonreliefangle="90 Angle" smdpad.airgapwidth=10 via.connectstyle=Relief via.reliefconductorwidth=10 via.reliefentries=4 via.polygonreliefangle="90 Angle" via.airgapwidth=10
PolygonConnect PolygonConnect_89 [All vs IsNamedPolygon('TOP_LAYER_BOUT1_P240')] p6: thpad.connectstyle=Direct thpad.reliefconductorwidth=10 thpad.reliefentries=4 thpad.polygonreliefangle="90 Angle" thpad.airgapwidth=10 smdpad.connectstyle=Direct smdpad.reliefconductorwidth=10 smdpad.reliefentries=4 smdpad.polygonreliefangle="90 Angle" smdpad.airgapwidth=10 via.connectstyle=Relief via.reliefconductorwidth=10 via.reliefentries=4 via.polygonreliefangle="90 Angle" via.airgapwidth=10
PolygonConnect PolygonConnect_88 [All vs IsNamedPolygon('BOTTOM_LAYER_VM_P080')] p7: thpad.connectstyle=Direct thpad.reliefconductorwidth=10 thpad.reliefentries=4 thpad.polygonreliefangle="90 Angle" thpad.airgapwidth=10 smdpad.connectstyle=Direct smdpad.reliefconductorwidth=10 smdpad.reliefentries=4 smdpad.polygonreliefangle="90 Angle" smdpad.airgapwidth=10 via.connectstyle=Relief via.reliefconductorwidth=10 via.reliefentries=4 via.polygonreliefangle="90 Angle" via.airgapwidth=10
PolygonConnect PolygonConnect_87 [All vs IsNamedPolygon('TOP_LAYER_VM_P125')] p8: connectstyle=Direct reliefconductorwidth=10 reliefentries=4 polygonreliefangle="90 Angle" airgapwidth=10
PolygonConnect PolygonConnect_86 [All vs IsNamedPolygon('BOTTOM_LAYER_VM_P080')] p9: connectstyle=Direct reliefconductorwidth=10 reliefentries=4 polygonreliefangle="90 Angle" airgapwidth=10
PolygonConnect PolygonConnect_85 [All vs IsNamedPolygon('BOTTOM_LAYER_OUT2_P211')] p10: connectstyle=Direct reliefconductorwidth=10 reliefentries=4 polygonreliefangle="90 Angle" airgapwidth=10
PolygonConnect PolygonConnect_84 [All vs IsNamedPolygon('BOTTOM_LAYER_OUT1_P205')] p11: connectstyle=Direct reliefconductorwidth=10 reliefentries=4 polygonreliefangle="90 Angle" airgapwidth=10
PolygonConnect PolygonConnect_83 [All vs IsNamedPolygon('BOTTOM_LAYER_OUT1_P205')] p12: connectstyle=Direct reliefconductorwidth=10 reliefentries=4 polygonreliefangle="90 Angle" airgapwidth=10
PolygonConnect PolygonConnect_82 [All vs IsNamedPolygon('BOTTOM_LAYER_GND_P204')] p13: connectstyle=Direct reliefconductorwidth=10 reliefentries=4 polygonreliefangle="90 Angle" airgapwidth=10
PolygonConnect PolygonConnect_81 [All vs IsNamedPolygon('TOP_LAYER_NONET_P237')] p14: connectstyle=Direct reliefconductorwidth=10 reliefentries=4 polygonreliefangle="90 Angle" airgapwidth=10
PolygonConnect PolygonConnect_80 [All vs IsNamedPolygon('TOP_LAYER_GND_P086')] p15: connectstyle=Direct reliefconductorwidth=10 reliefentries=4 polygonreliefangle="90 Angle" airgapwidth=10
PolygonConnect PolygonConnect_79 [All vs IsNamedPolygon('TOP_LAYER_VM_P229')] p16: connectstyle=Direct reliefconductorwidth=10 reliefentries=4 polygonreliefangle="90 Angle" airgapwidth=10
PolygonConnect PolygonConnect_78 [All vs IsNamedPolygon('TOP_LAYER_GND_P086')] p17: connectstyle=Direct reliefconductorwidth=10 reliefentries=4 polygonreliefangle="90 Angle" airgapwidth=10
PolygonConnect PolygonConnect_77 [All vs IsNamedPolygon('TOP_LAYER_OUT1_P221')] p18: connectstyle=Direct reliefconductorwidth=10 reliefentries=4 polygonreliefangle="90 Angle" airgapwidth=10
PolygonConnect PolygonConnect_76 [All vs IsNamedPolygon('TOP_LAYER_OUT2_P173')] p19: connectstyle=Direct reliefconductorwidth=10 reliefentries=4 polygonreliefangle="90 Angle" airgapwidth=10
PolygonConnect PolygonConnect_75 [All vs IsNamedPolygon('TOP_LAYER_OUT2_P173')] p20: connectstyle=Direct reliefconductorwidth=10 reliefentries=4 polygonreliefangle="90 Angle" airgapwidth=10
PolygonConnect PolygonConnect_74 [All vs IsNamedPolygon('TOP_LAYER_OUT2_P173')] p21: connectstyle=Direct reliefconductorwidth=10 reliefentries=4 polygonreliefangle="90 Angle" airgapwidth=10
PolygonConnect PolygonConnect_73 [All vs IsNamedPolygon('TOP_LAYER_OUT1_P221')] p22: connectstyle=Direct reliefconductorwidth=10 reliefentries=4 polygonreliefangle="90 Angle" airgapwidth=10
PolygonConnect PolygonConnect_72 [All vs IsNamedPolygon('TOP_LAYER_GND_P121')] p23: connectstyle=Direct reliefconductorwidth=10 reliefentries=4 polygonreliefangle="90 Angle" airgapwidth=10
PolygonConnect PolygonConnect_71 [All vs IsNamedPolygon('TOP_LAYER_OUT2_P173') Or  IsNamedPolygon('TOP_LAYER_OUT1_P129')] p24: connectstyle=Direct reliefconductorwidth=10 reliefentries=4 polygonreliefangle="90 Angle" airgapwidth=10
PolygonConnect PolygonConnect_70 [All vs IsNamedPolygon('TOP_LAYER_OUT2_P173')] p25: connectstyle=Direct reliefconductorwidth=10 reliefentries=4 polygonreliefangle="90 Angle" airgapwidth=10
PolygonConnect PolygonConnect_69 [All vs IsNamedPolygon('TOP_LAYER_OUT1_P129')] p26: connectstyle=Direct reliefconductorwidth=10 reliefentries=4 polygonreliefangle="90 Angle" airgapwidth=10
PolygonConnect PolygonConnect_68 [All vs IsNamedPolygon('TOP_LAYER_VM_P085')] p27: connectstyle=Direct reliefconductorwidth=10 reliefentries=4 polygonreliefangle="90 Angle" airgapwidth=10
PolygonConnect PolygonConnect_67 [All vs IsNamedPolygon('BOTTOM_LAYER_P_IN_P174')] p28: connectstyle=Direct reliefconductorwidth=10 reliefentries=4 polygonreliefangle="90 Angle" airgapwidth=10
PolygonConnect PolygonConnect_66 [All vs IsNamedPolygon('BOTTOM_LAYER_NETF1_2_P203')] p29: connectstyle=Direct reliefconductorwidth=10 reliefentries=4 polygonreliefangle="90 Angle" airgapwidth=10
PolygonConnect PolygonConnect_65 [All vs IsNamedPolygon('BOTTOM_LAYER_VBAT_P165')] p30: connectstyle=Direct reliefconductorwidth=10 reliefentries=4 polygonreliefangle="90 Angle" airgapwidth=10
PolygonConnect PolygonConnect_64 [All vs IsNamedPolygon('TOP_LAYER_VM_P167')] p31: connectstyle=Direct reliefconductorwidth=10 reliefentries=4 polygonreliefangle="90 Angle" airgapwidth=10
PolygonConnect PolygonConnect_63 [All vs IsNamedPolygon('TOP_LAYER_VM_P167')] p32: connectstyle=Direct reliefconductorwidth=10 reliefentries=4 polygonreliefangle="90 Angle" airgapwidth=10
PolygonConnect PolygonConnect_62 [All vs IsNamedPolygon('TOP_LAYER_VM_P171')] p33: connectstyle=Direct reliefconductorwidth=10 reliefentries=4 polygonreliefangle="90 Angle" airgapwidth=10
PolygonConnect PolygonConnect_61 [All vs IsNamedPolygon('SIGNAL_LAYER_2_GND_P199')] p34: connectstyle=Direct reliefconductorwidth=10 reliefentries=4 polygonreliefangle="90 Angle" airgapwidth=10
PolygonConnect PolygonConnect_60 [All vs IsNamedPolygon('SIGNAL_LAYER_2_NETF1_2_P196')] p35: connectstyle=Direct reliefconductorwidth=10 reliefentries=4 polygonreliefangle="90 Angle" airgapwidth=10
PolygonConnect PolygonConnect_59 [All vs IsNamedPolygon('SIGNAL_LAYER_2_VBAT_P197')] p36: connectstyle=Direct reliefconductorwidth=10 reliefentries=4 polygonreliefangle="90 Angle" airgapwidth=10
PolygonConnect PolygonConnect_58 [All vs IsNamedPolygon('SIGNAL_LAYER_2_P_IN_P198')] p37: connectstyle=Direct reliefconductorwidth=10 reliefentries=4 polygonreliefangle="90 Angle" airgapwidth=10
PolygonConnect PolygonConnect_57 [All vs IsNamedPolygon('SIGNAL_LAYER_2_3V3_P194')] p38: connectstyle=Direct reliefconductorwidth=10 reliefentries=4 polygonreliefangle="90 Angle" airgapwidth=10
PolygonConnect PolygonConnect_56 [All vs IsNamedPolygon('TOP_LAYER_NETF1_2_P207')] p39: connectstyle=Direct reliefconductorwidth=10 reliefentries=4 polygonreliefangle="90 Angle" airgapwidth=10
PolygonConnect PolygonConnect_55 [All vs IsNamedPolygon('TOP_LAYER_VBAT_P223')] p40: connectstyle=Direct reliefconductorwidth=10 reliefentries=4 polygonreliefangle="90 Angle" airgapwidth=10
PolygonConnect PolygonConnect_54 [All vs IsNamedPolygon('TOP_LAYER_P_IN_P227')] p41: connectstyle=Direct reliefconductorwidth=10 reliefentries=4 polygonreliefangle="90 Angle" airgapwidth=10
PolygonConnect PolygonConnect_53 [All vs IsNamedPolygon('TOP_LAYER_GND_P086')] p42: connectstyle=Direct reliefconductorwidth=10 reliefentries=4 polygonreliefangle="90 Angle" airgapwidth=10
PolygonConnect PolygonConnect_52 [All vs IsNamedPolygon('SIGNAL_LAYER_2_VM_P177') Or  IsNamedPolygon('SIGNAL_LAYER_2_VM_P179') Or  IsNamedPolygon('SIGNAL_LAYER_2_VM_P160') Or  IsNamedPolygon('SIGNAL_LAYER_2_VM_P175') Or  IsNamedPolygon('SIGNAL_LAYER_2_VM_P181')] p43: connectstyle=Direct reliefconductorwidth=10 reliefentries=4 polygonreliefangle="90 Angle" airgapwidth=10
PolygonConnect PolygonConnect_51 [All vs IsNamedPolygon('SIGNAL_LAYER_2_EZFET_VBUS_P136')] p44: connectstyle=Direct reliefconductorwidth=10 reliefentries=4 polygonreliefangle="90 Angle" airgapwidth=10
PolygonConnect PolygonConnect_50 [All vs IsNamedPolygon('SIGNAL_LAYER_2_EZFET_VCC_P132')] p45: connectstyle=Direct reliefconductorwidth=10 reliefentries=4 polygonreliefangle="90 Angle" airgapwidth=10
PolygonConnect PolygonConnect_49 [All vs IsNamedPolygon('SIGNAL_LAYER_2_MCU_3V3_P192')] p46: connectstyle=Direct reliefconductorwidth=10 reliefentries=4 polygonreliefangle="90 Angle" airgapwidth=10
PolygonConnect PolygonConnect_48 [All vs IsNamedPolygon('SIGNAL_LAYER_1_GND_P190')] p47: connectstyle=Direct reliefconductorwidth=10 reliefentries=4 polygonreliefangle="90 Angle" airgapwidth=10
PolygonConnect PolygonConnect_47 [All vs IsNamedPolygon('SIGNAL_LAYER_1_GND_P184')] p48: connectstyle=Direct reliefconductorwidth=10 reliefentries=4 polygonreliefangle="90 Angle" airgapwidth=10
PolygonConnect PolygonConnect_46 [All vs IsNamedPolygon('BOTTOM_LAYER_GND_P241')] p49: connectstyle=Direct reliefconductorwidth=10 reliefentries=4 polygonreliefangle="90 Angle" airgapwidth=10
PolygonConnect PolygonConnect_45 [All vs IsNamedPolygon('BOTTOM_LAYER_GND_P241')] p50: connectstyle=Direct reliefconductorwidth=10 reliefentries=4 polygonreliefangle="90 Angle" airgapwidth=10
PolygonConnect PolygonConnect_44 [All vs IsNamedPolygon('BOTTOM_LAYER_OUT2_P163')] p51: connectstyle=Direct reliefconductorwidth=10 reliefentries=4 polygonreliefangle="90 Angle" airgapwidth=10
PolygonConnect PolygonConnect_43 [All vs IsNamedPolygon('BOTTOM_LAYER_VM_P166')] p52: connectstyle=Direct reliefconductorwidth=10 reliefentries=4 polygonreliefangle="90 Angle" airgapwidth=10
PolygonConnect PolygonConnect_42 [All vs IsNamedPolygon('BOTTOM_LAYER_VM_P235')] p53: connectstyle=Direct reliefconductorwidth=10 reliefentries=4 polygonreliefangle="90 Angle" airgapwidth=10
PolygonConnect PolygonConnect_41 [All vs IsNamedPolygon('BOTTOM_LAYER_OUT1_P164')] p54: connectstyle=Direct reliefconductorwidth=10 reliefentries=4 polygonreliefangle="90 Angle" airgapwidth=10
PolygonConnect PolygonConnect_40 [All vs IsNamedPolygon('BOTTOM_LAYER_GND_P162')] p55: connectstyle=Direct reliefconductorwidth=10 reliefentries=4 polygonreliefangle="90 Angle" airgapwidth=10
PolygonConnect PolygonConnect_39 [All vs IsNamedPolygon('SIGNAL_LAYER_2_VM_P160')] p56: connectstyle=Direct reliefconductorwidth=10 reliefentries=4 polygonreliefangle="90 Angle" airgapwidth=10
PolygonConnect PolygonConnect_38 [All vs IsNamedPolygon('SIGNAL_LAYER_2_NONET_P138')] p57: connectstyle=Direct reliefconductorwidth=10 reliefentries=4 polygonreliefangle="90 Angle" airgapwidth=10
PolygonConnect PolygonConnect_37 [All vs IsNamedPolygon('SIGNAL_LAYER_1_VM_P146')] p58: connectstyle=Direct reliefconductorwidth=10 reliefentries=4 polygonreliefangle="90 Angle" airgapwidth=10
PolygonConnect PolygonConnect_36 [All vs IsNamedPolygon('SIGNAL_LAYER_2_GND_P156')] p59: connectstyle=Direct reliefconductorwidth=10 reliefentries=4 polygonreliefangle="90 Angle" airgapwidth=10
PolygonConnect PolygonConnect_35 [All vs IsNamedPolygon('BOTTOM_LAYER_EZFET_USB_SHIELD_P219')] p60: connectstyle=Direct reliefconductorwidth=10 reliefentries=4 polygonreliefangle="90 Angle" airgapwidth=10
PolygonConnect PolygonConnect_34 [All vs IsNamedPolygon('SIGNAL_LAYER_1_VM_P144')] p61: connectstyle=Direct reliefconductorwidth=10 reliefentries=4 polygonreliefangle="90 Angle" airgapwidth=10
PolygonConnect PolygonConnect_33 [All vs IsNamedPolygon('SIGNAL_LAYER_1_VM_P148') Or  IsNamedPolygon('SIGNAL_LAYER_1_VM_P148')] p62: connectstyle=Direct reliefconductorwidth=10 reliefentries=4 polygonreliefangle="90 Angle" airgapwidth=10
PolygonConnect PolygonConnect_32 [All vs IsNamedPolygon('SIGNAL_LAYER_1_GND_P154')] p63: connectstyle=Direct reliefconductorwidth=10 reliefentries=4 polygonreliefangle="90 Angle" airgapwidth=10
PolygonConnect PolygonConnect_31 [All vs IsNamedPolygon('SIGNAL_LAYER_2_NONET_P138')] p64: connectstyle=Direct reliefconductorwidth=10 reliefentries=4 polygonreliefangle="90 Angle" airgapwidth=10
PolygonConnect PolygonConnect_30 [All vs IsNamedPolygon('SIGNAL_LAYER_2_GND_P082')] p65: connectstyle=Direct reliefconductorwidth=10 reliefentries=4 polygonreliefangle="90 Angle" airgapwidth=10
PolygonConnect PolygonConnect_29 [All vs IsNamedPolygon('TOP_LAYER_GND_P076')] p66: connectstyle=Direct reliefconductorwidth=10 reliefentries=4 polygonreliefangle="90 Angle" airgapwidth=10
PolygonConnect PolygonConnect_28 [All vs IsNamedPolygon('TOP_LAYER_GND_P087')] p67: connectstyle=Direct reliefconductorwidth=10 reliefentries=4 polygonreliefangle="90 Angle" airgapwidth=10
PolygonConnect PolygonConnect_27 [All vs IsNamedPolygon('TOP_LAYER_VM_P127') Or  IsNamedPolygon('TOP_LAYER_VM_P085')] p68: connectstyle=Direct reliefconductorwidth=10 reliefentries=4 polygonreliefangle="90 Angle" airgapwidth=10
PolygonConnect PolygonConnect_26 [All vs IsNamedPolygon('TOP_LAYER_GND_P117')] p69: connectstyle=Direct reliefconductorwidth=10 reliefentries=4 polygonreliefangle="90 Angle" airgapwidth=10
PolygonConnect PolygonConnect_25 [All vs IsNamedPolygon('TOP_LAYER_OUT1_P129') Or  IsNamedPolygon('TOP_LAYER_OUT2_P173')] p70: connectstyle=Direct reliefconductorwidth=10 reliefentries=4 polygonreliefangle="90 Angle" airgapwidth=10
PolygonConnect PolygonConnect_24 [All vs IsNamedPolygon('SIGNAL_LAYER_2_NONET_P113')] p71: connectstyle=Direct reliefconductorwidth=10 reliefentries=4 polygonreliefangle="90 Angle" airgapwidth=10
PolygonConnect PolygonConnect_23 [All vs IsNamedPolygon('BOTTOM_LAYER_NONET_P115')] p72: connectstyle=Direct reliefconductorwidth=10 reliefentries=4 polygonreliefangle="90 Angle" airgapwidth=10
PolygonConnect PolygonConnect_22 [All vs IsNamedPolygon('SIGNAL_LAYER_1_NONET_P111')] p73: connectstyle=Direct reliefconductorwidth=10 reliefentries=4 polygonreliefangle="90 Angle" airgapwidth=10
PolygonConnect PolygonConnect_21 [All vs IsNamedPolygon('TOP_LAYER_NONET_P083')] p74: connectstyle=Direct reliefconductorwidth=10 reliefentries=4 polygonreliefangle="90 Angle" airgapwidth=10
PolygonConnect PolygonConnect_20 [All vs IsNamedPolygon('TOP_LAYER_NONET_P105')] p75: connectstyle=Direct reliefconductorwidth=10 reliefentries=4 polygonreliefangle="90 Angle" airgapwidth=10
PolygonConnect PolygonConnect_19 [All vs IsNamedPolygon('TOP_LAYER_OUT2_P107')] p76: connectstyle=Direct reliefconductorwidth=10 reliefentries=4 polygonreliefangle="90 Angle" airgapwidth=10
PolygonConnect PolygonConnect_18 [All vs IsNamedPolygon('TOP_LAYER_NONET_P101')] p77: connectstyle=Direct reliefconductorwidth=10 reliefentries=4 polygonreliefangle="90 Angle" airgapwidth=10
PolygonConnect PolygonConnect_17 [All vs IsNamedPolygon('TOP_LAYER_OUT1_P103')] p78: connectstyle=Direct reliefconductorwidth=10 reliefentries=4 polygonreliefangle="90 Angle" airgapwidth=10
PolygonConnect PolygonConnect_16 [All vs IsNamedPolygon('TOP_LAYER_OUT1_P000')] p79: connectstyle=Direct reliefconductorwidth=10 reliefentries=4 polygonreliefangle="90 Angle" airgapwidth=10
PolygonConnect PolygonConnect_15 [All vs IsNamedPolygon('TOP_LAYER_NONET_P093')] p80: connectstyle=Direct reliefconductorwidth=10 reliefentries=4 polygonreliefangle="90 Angle" airgapwidth=10
PolygonConnect PolygonConnect_14 [All vs IsNamedPolygon('TOP_LAYER_OUT2_P099')] p81: connectstyle=Direct reliefconductorwidth=10 reliefentries=4 polygonreliefangle="90 Angle" airgapwidth=10
PolygonConnect PolygonConnect_13 [All vs IsNamedPolygon('TOP_LAYER_OUT1_P000')] p82: connectstyle=Direct reliefconductorwidth=10 reliefentries=4 polygonreliefangle="90 Angle" airgapwidth=10
PolygonConnect PolygonConnect_12 [All vs IsNamedPolygon('BOTTOM_LAYER_NONET_P079') Or  IsNamedPolygon('SIGNAL_LAYER_2_NONET_P078') Or  IsNamedPolygon('SIGNAL_LAYER_1_NONET_P077') Or  IsNamedPolygon('TOP_LAYER_NONET_P083') Or  IsNamedPolygon('BOTTOM_LAYER_NONET_P072') Or  IsNamedPolygon('SIGNAL_LAYER_2_NONET_P070') Or  IsNamedPolygon('SIGNAL_LAYER_1_NONET_P059') Or  IsNamedPolygon('TOP_LAYER_OUT2_P058') Or  IsNamedPolygon('BOTTOM_LAYER_NONET_P056') Or  IsNamedPolygon('SIGNAL_LAYER_2_NONET_P054') Or  IsNamedPolygon('SIGNAL_LAYER_1_NONET_P052') Or  IsNamedPolygon('TOP_LAYER_OUT1_P050') Or  IsNamedPolygon('BOTTOM_LAYER_VM_P044') Or  IsNamedPolygon('SIGNAL_LAYER_2_VM_P042') Or  IsNamedPolygon('SIGNAL_LAYER_1_VM_P040') Or  IsNamedPolygon('TOP_LAYER_VM_P038') Or  IsNamedPolygon('BOTTOM_LAYER_VM_P036') Or  IsNamedPolygon('SIGNAL_LAYER_2_VM_P018') Or  IsNamedPolygon('SIGNAL_LAYER_1_VM_P016') Or  IsNamedPolygon('TOP_LAYER_VM_P002')] p83: connectstyle=Direct reliefconductorwidth=10 reliefentries=4 polygonreliefangle="90 Angle" airgapwidth=10
PolygonConnect PolygonConnect_11 [All vs IsNamedPolygon('TOP_LAYER_NONET_P089') Or  IsNamedPolygon('TOP_LAYER_NONET_P090')] p84: connectstyle=Direct reliefconductorwidth=10 reliefentries=4 polygonreliefangle="90 Angle" airgapwidth=10
PolygonConnect PolygonConnect_10 [All vs IsNamedPolygon('BOTTOM_LAYER_EZFET_USB_SHIELD_P002') Or  IsNamedPolygon('TOP_LAYER_EZFET_USB_SHIELD_P201') Or  IsNamedPolygon('SIGNAL_LAYER_2_EZFET_VBUS_P018') Or  IsNamedPolygon('SIGNAL_LAYER_2_EZFET_VCC_P016')] p85: connectstyle=Direct reliefconductorwidth=10 reliefentries=4 polygonreliefangle="90 Angle" airgapwidth=10
PolygonConnect PolygonConnect_9 [All vs IsNamedPolygon('TOP_LAYER_VM_P123') Or  IsNamedPolygon('TOP_LAYER_VM_P123') Or  IsNamedPolygon('TOP_LAYER_VM_P123')] p86: connectstyle=Direct reliefconductorwidth=10 reliefentries=4 polygonreliefangle="90 Angle" airgapwidth=10
PolygonConnect PolygonConnect_8 [All vs IsNamedPolygon('TOP_LAYER_NONET_P072')] p87: connectstyle=Direct reliefconductorwidth=10 reliefentries=4 polygonreliefangle="90 Angle" airgapwidth=10
PolygonConnect PolygonConnect_7 [All vs IsNamedPolygon('TOP_LAYER_NONET_P072')] p88: connectstyle=Direct reliefconductorwidth=10 reliefentries=4 polygonreliefangle="90 Angle" airgapwidth=10
PolygonConnect PolygonConnect_6 [All vs IsNamedPolygon('TOP_LAYER_VM_P042')] p89: connectstyle=Direct reliefconductorwidth=10 reliefentries=4 polygonreliefangle="90 Angle" airgapwidth=10
PolygonConnect PolygonConnect_5 [All vs IsNamedPolygon('TOP_LAYER_VM_P044')] p90: connectstyle=Direct reliefconductorwidth=10 reliefentries=4 polygonreliefangle="90 Angle" airgapwidth=10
